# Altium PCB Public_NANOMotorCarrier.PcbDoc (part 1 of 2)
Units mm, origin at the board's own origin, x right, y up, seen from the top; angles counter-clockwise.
Board outline 50 x 80 mm, 4 copper layers (Top, PWR, GND, Bottom), stack 1.612 mm thick; 200 components, 139 nets, 723 pads, 320 vias.
Unrouted connection lines stored in the file: 53.
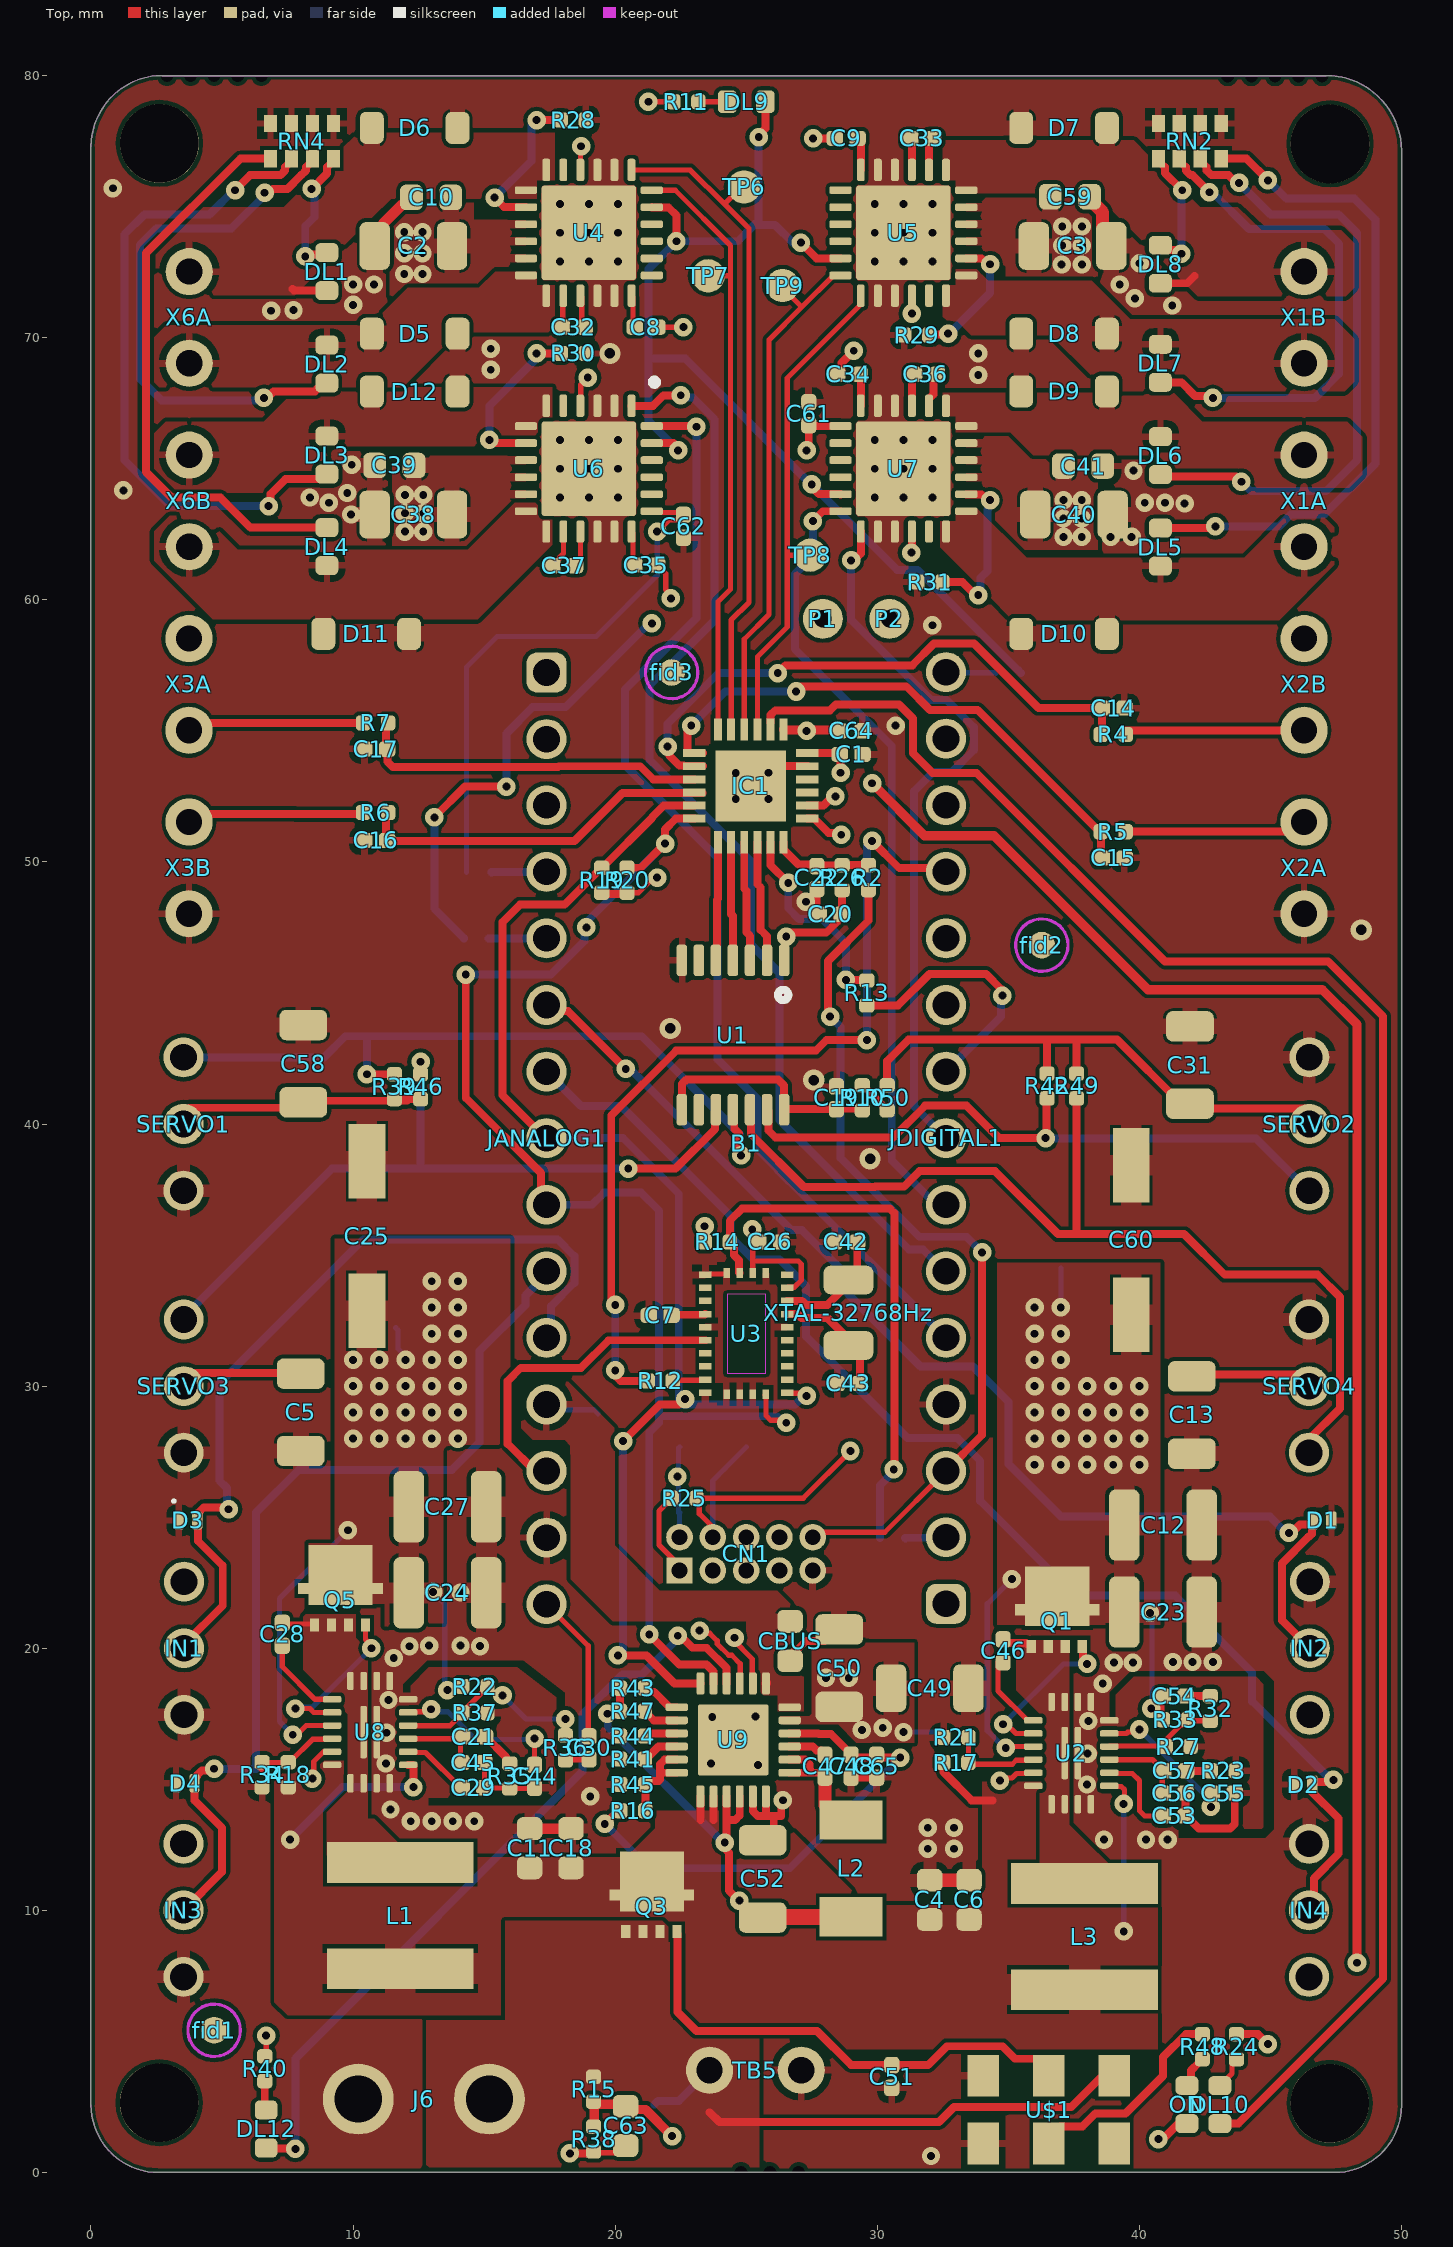
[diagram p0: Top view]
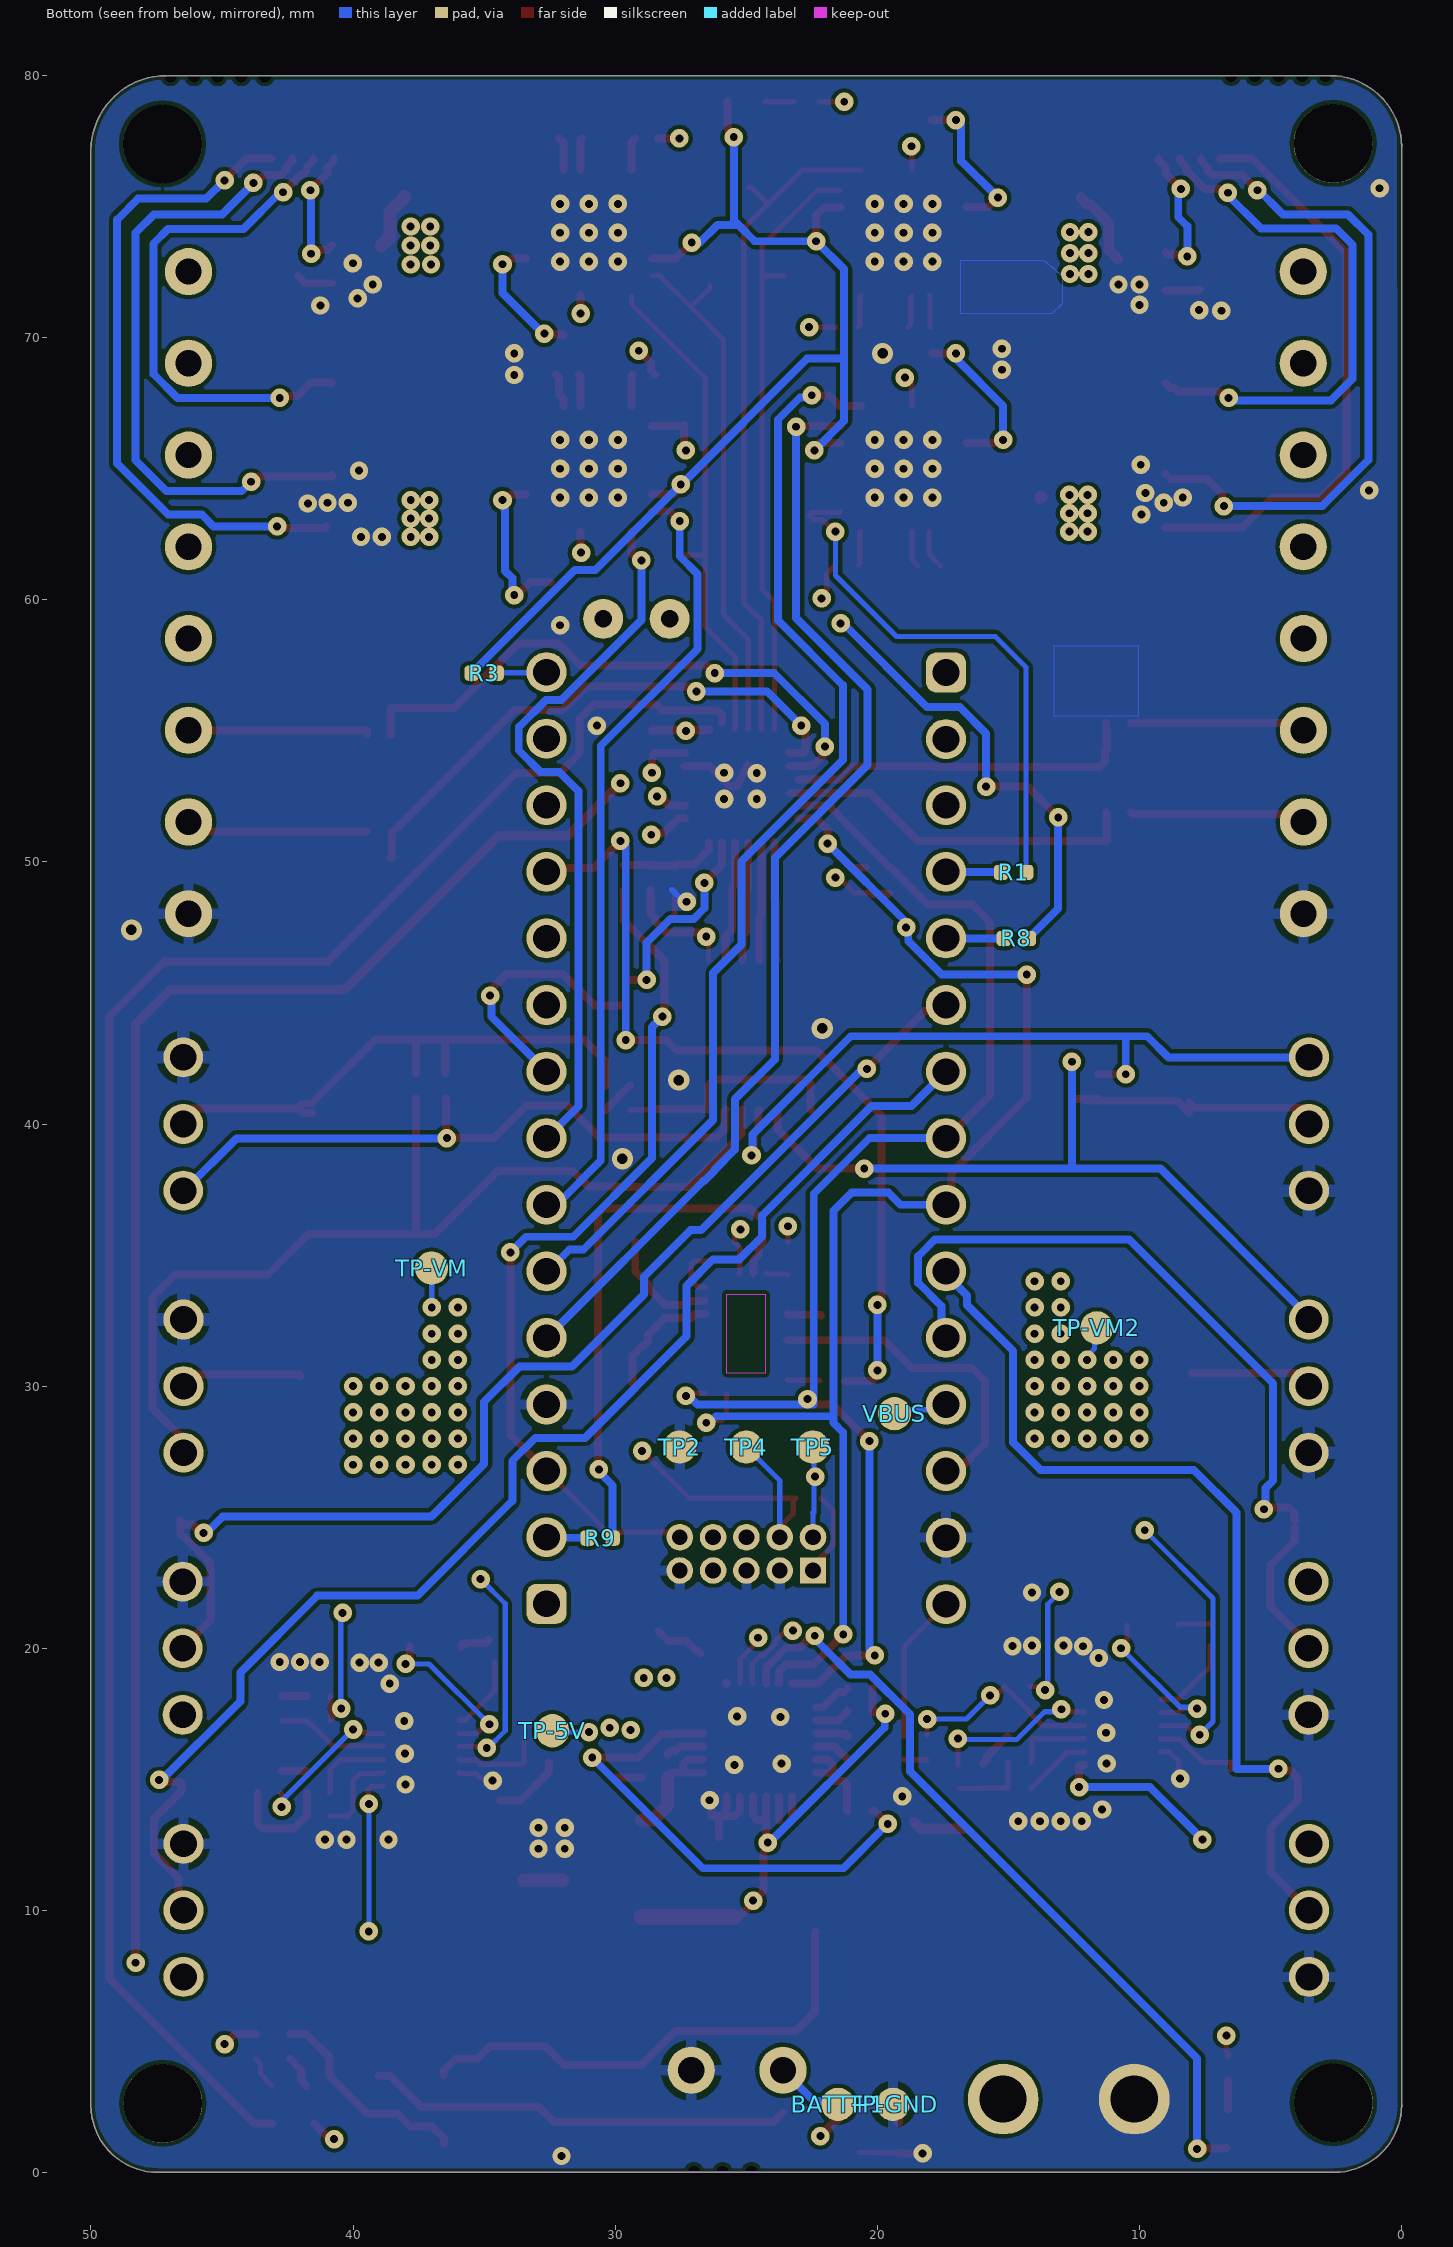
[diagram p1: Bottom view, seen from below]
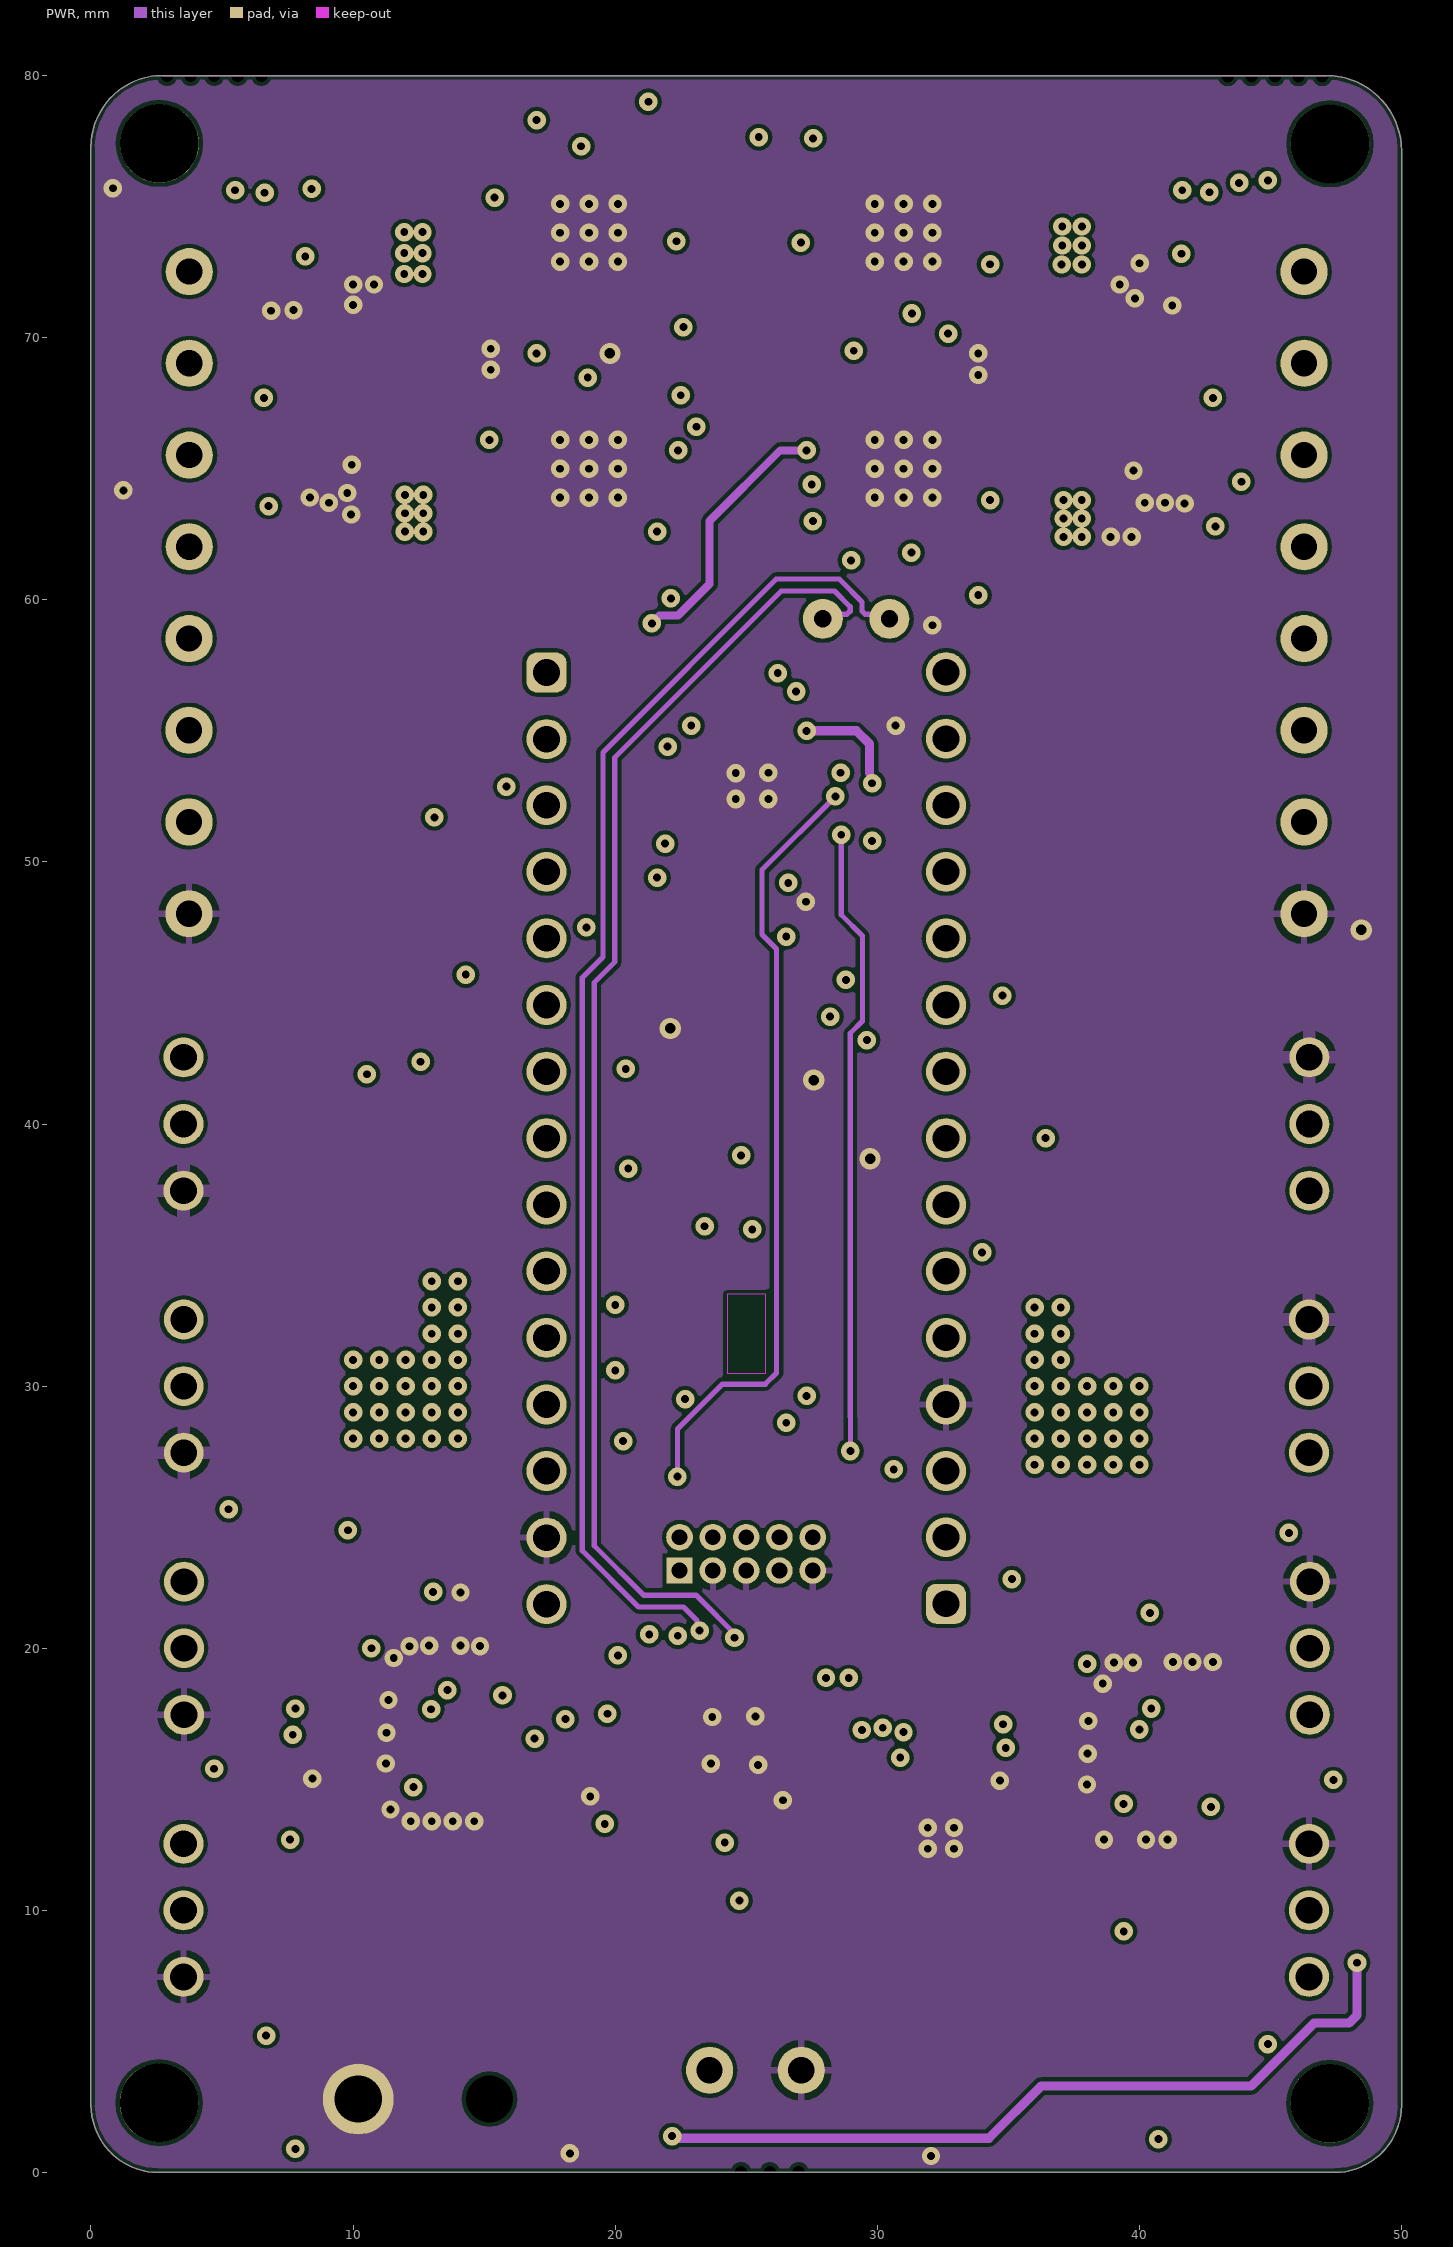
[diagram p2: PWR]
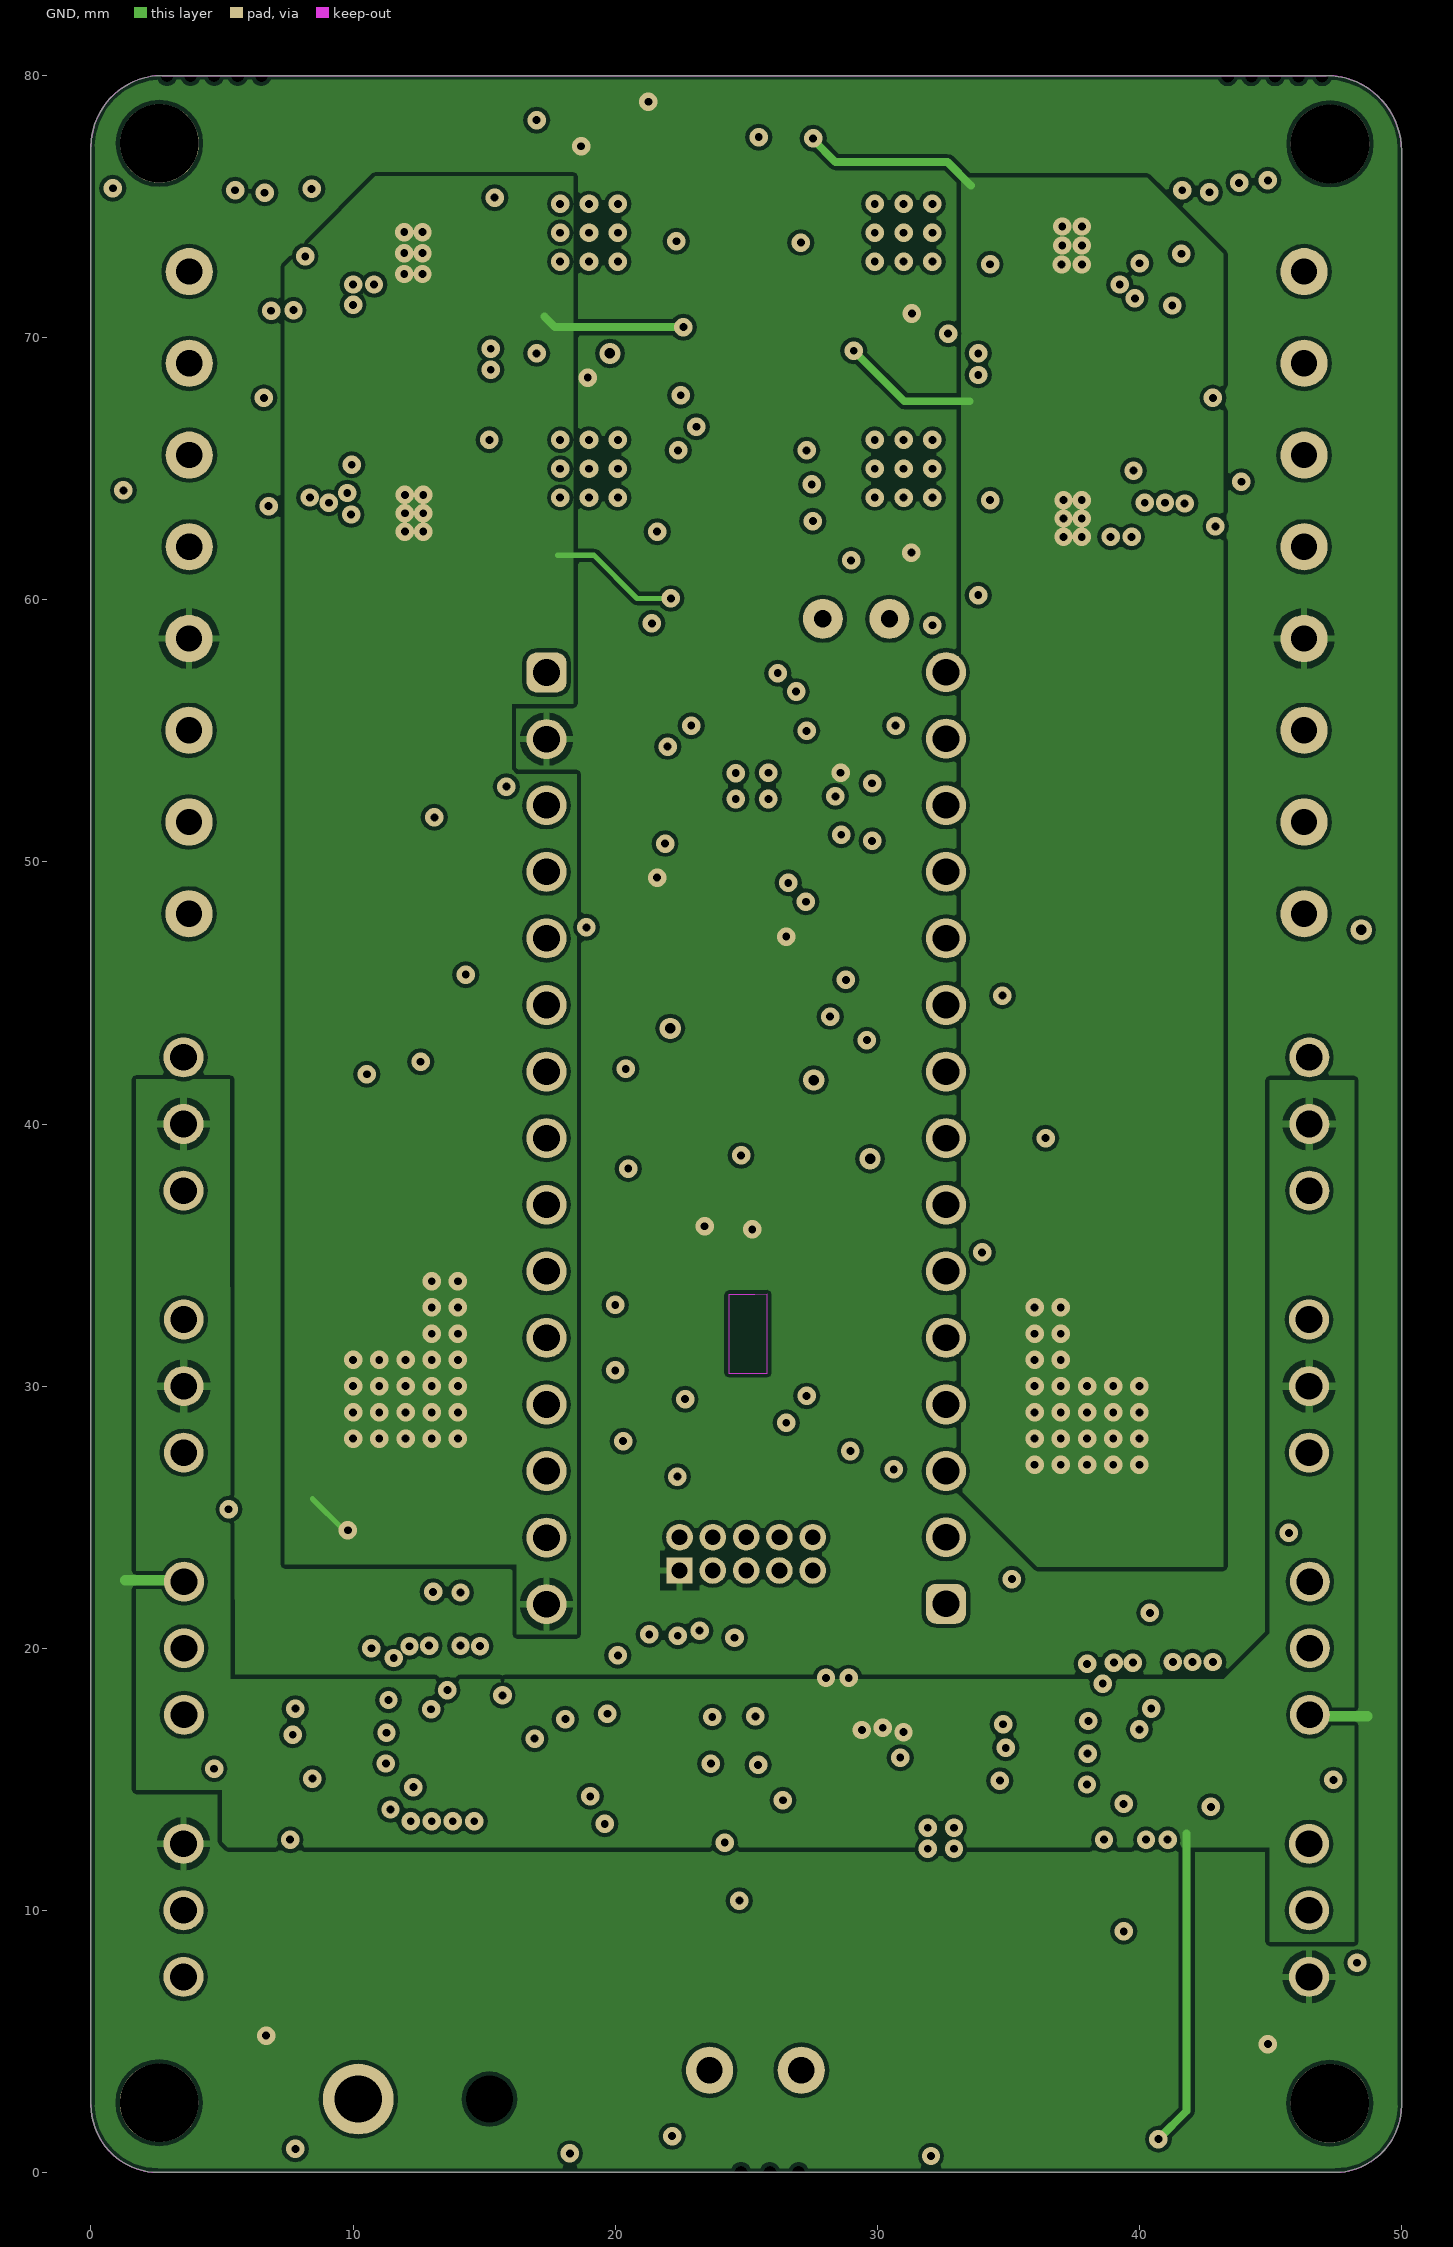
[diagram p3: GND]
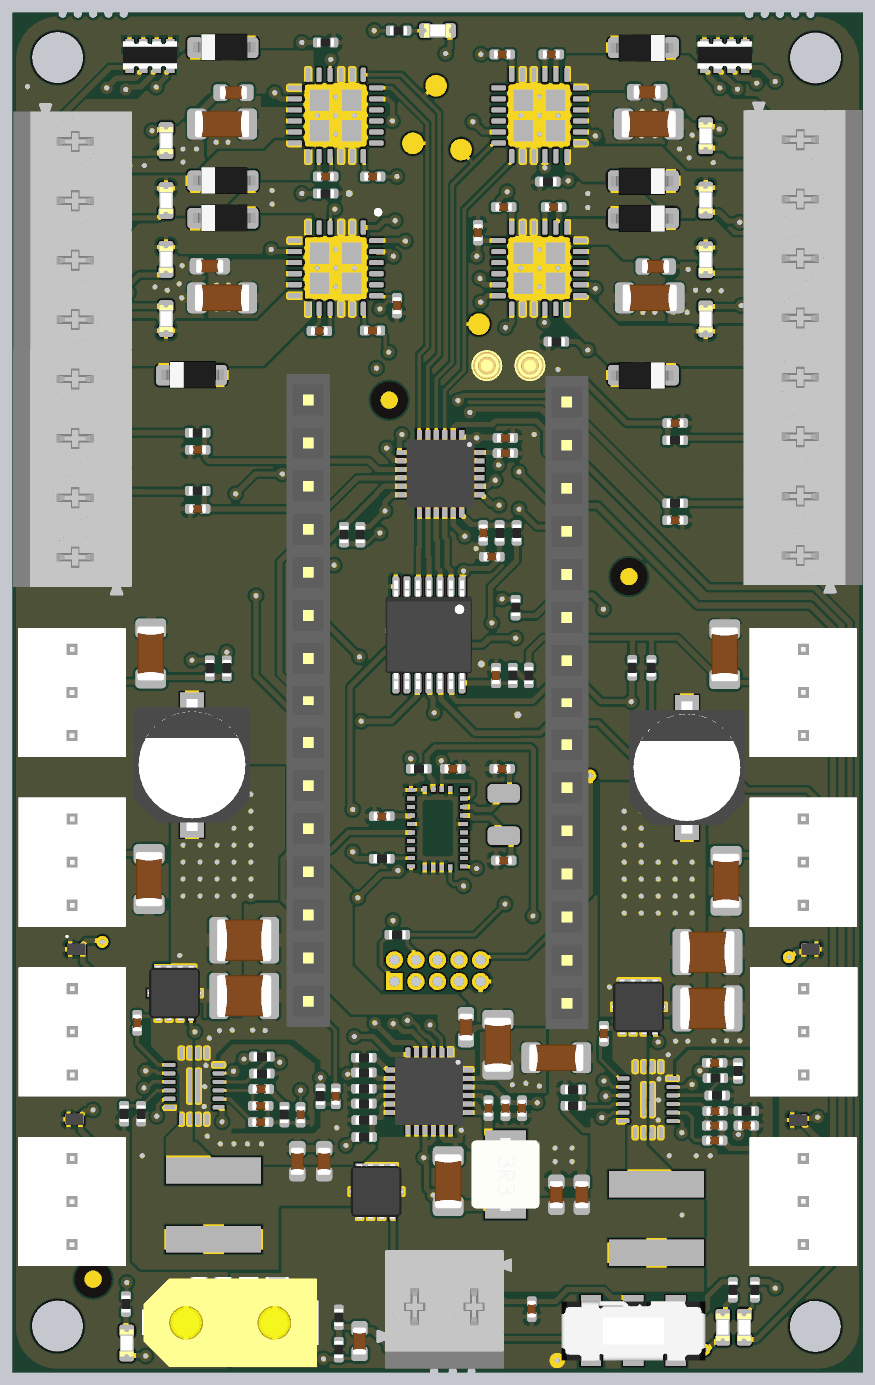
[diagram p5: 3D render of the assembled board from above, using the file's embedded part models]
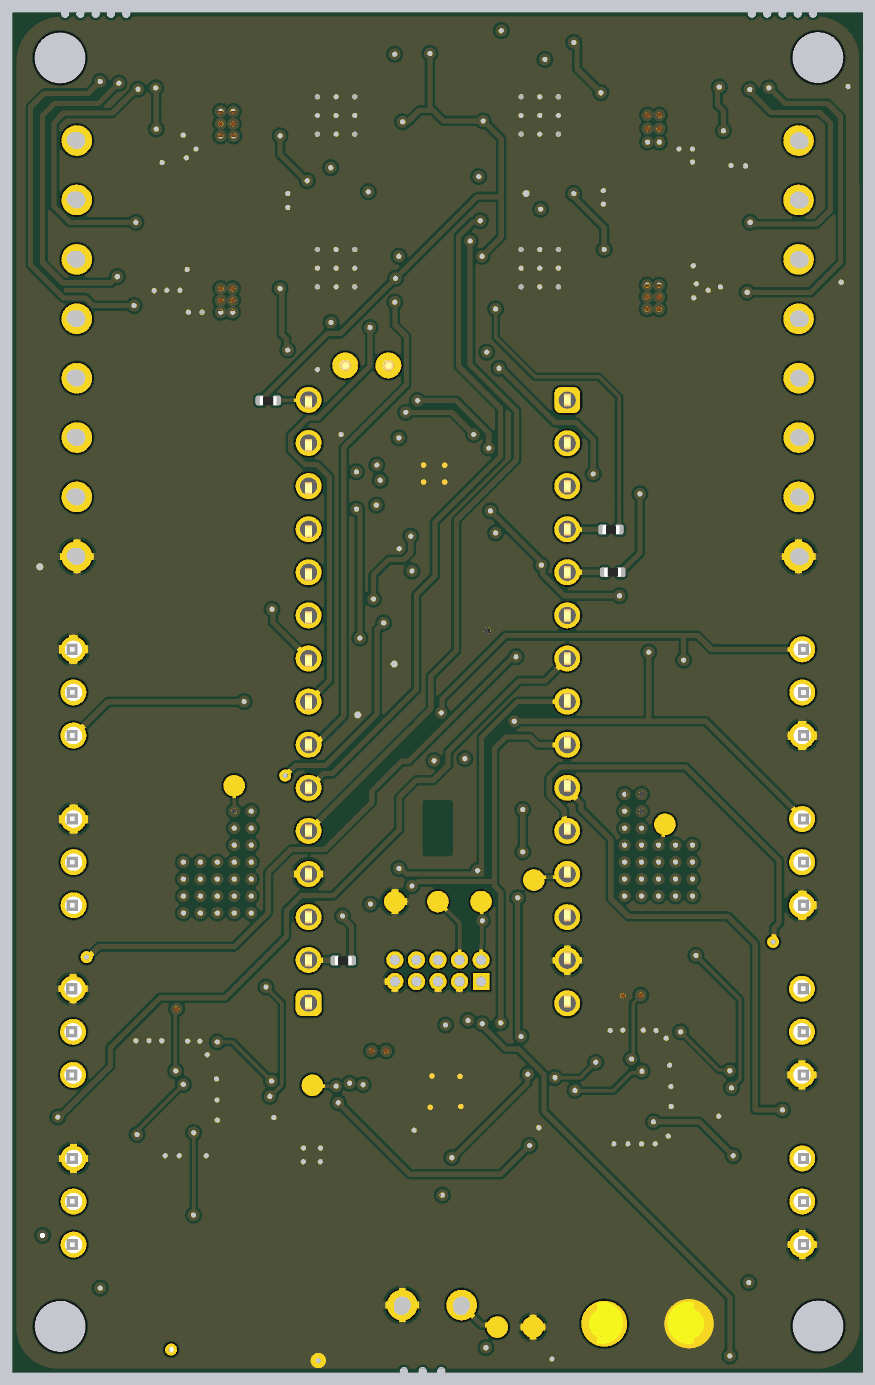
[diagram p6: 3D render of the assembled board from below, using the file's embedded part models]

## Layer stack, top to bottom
Top Solder: solder mask 0.01, Solder Resist, Dk 3.5
Top: signal copper 0.035
Dielectric 1: prepreg 0.356, FR-4, Dk 4.1
PWR: signal copper 0.035
Dielectric3: core 0.76, FR-4, Dk 4.8
GND: signal copper 0.035
Dielectric2: prepreg 0.356, FR-4, Dk 4.1
Bottom: signal copper 0.035
Bottom Solder: solder mask 0.0102, Solder Resist, Dk 3.5

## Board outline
47.437,0 2.583,0 cw(c2.583,2.583) 0,2.583 0,77.275 cw(c2.725,77.275) 2.725,80 47.122,80 cw(c47.122,77.122) 50,77.122 50,2.563 cw(c47.437,2.563)

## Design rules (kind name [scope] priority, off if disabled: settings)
Clearance "Clearance (Same Net)" [All] p1 off: gap=0.178 ignorepadtopadclearanceinfootprint=FALSE except(0.152: SMDPad-SMDPad SMDPad-THPad SMDPad-Via)
Clearance [All] p2: gap=0.15 ignorepadtopadclearanceinfootprint=TRUE
DiffPairsRouting [All] p1: maxlimit=0.254 minlimit=0.254 mostfreqgap=0.254 toplayer_minwidth=0.2 toplayer_maxwidth=0.381 toplayer_prefwidth=0.2 midlayer1_minwidth=0.2 midlayer1_maxwidth=0.381 midlayer1_prefwidth=0.2 midlayer2_minwidth=0.2 midlayer2_maxwidth=0.381 midlayer2_prefwidth=0.2 bottomlayer_minwidth=0.2 bottomlayer_maxwidth=0.381 bottomlayer_prefwidth=0.2 maxuncoupledlength=12.7
HoleSize [All] p1: absolutevalues=TRUE maxlimit=2540 minlimit=0.2 maxpercent=80.000 minpercent=20.000
HoleToHoleClearance NANO-CONNECTORS [InComponent('B1') vs InComponent('JDIGITAL1') or InComponent('JANALOG1')] p1: gap=0 allowstackedmicrovias=TRUE
HoleToHoleClearance mdDrill [All] p2: gap=0.254 allowstackedmicrovias=TRUE
MinimumSolderMaskSliver [All] p1 off: minsoldermaskwidth=0.254
PasteMaskExpansion Expansion_SMDPaste_OFF [InPadClass('SMDPaste_OFF')] p1: expansion=0
PasteMaskExpansion mlMinCreamFrame [All] p2: expansion=0
PlaneConnect PlaneConnect_1 [All] p1: planeconnectstyle=Relief reliefexpansion=0.508 reliefentries=4 reliefconductorwidth=0.254 reliefairgap=0.254
PolygonConnect VIA [IsVia] p1: connectstyle=Direct reliefconductorwidth=0.254 reliefentries=4 polygonreliefangle="90 Angle" airgapwidth=0.254
PolygonConnect SW_pad [(ObjectKind = 'Pad') And (Net = 'SW')] p2: connectstyle=Direct reliefconductorwidth=0.254 reliefentries=4 polygonreliefangle="90 Angle" airgapwidth=0.254
PolygonConnect +VM2_pad [(ObjectKind = 'Via') And (Net = '+VM2')] p3: connectstyle=Direct reliefconductorwidth=0.254 reliefentries=4 polygonreliefangle="90 Angle" airgapwidth=0.254
PolygonConnect VBATT_PADs [(ObjectKind = 'Pad') And (Net = 'VBATT')] p4: connectstyle=Direct reliefconductorwidth=0.254 reliefentries=4 polygonreliefangle="90 Angle" airgapwidth=0.254
PolygonConnect BATT+1_Pad [(ObjectKind = 'Pad') And (Net = 'BATT+1')] p5: connectstyle=Direct reliefconductorwidth=0.254 reliefentries=4 polygonreliefangle="90 Angle" airgapwidth=0.254
PolygonConnect GNDVias [IsVia and InNet('GND')] p6: connectstyle=Direct reliefconductorwidth=0.254 reliefentries=4 polygonreliefangle="90 Angle" airgapwidth=0.254
PolygonConnect MotorDriverGNDPads [IsComponentPad and InNet('GND') and InComponent('U4','U5','U6','U7')] p7: connectstyle=Direct reliefconductorwidth=0.254 reliefentries=4 polygonreliefangle="90 Angle" airgapwidth=0.254
PolygonConnect PolygonConnect_For_PolygonThermal_ON_Width120000_Gap100000 [InPolygonClass('PolygonThermal_ON_Width120000_Gap100000')] p8: connectstyle=Relief reliefconductorwidth=0.305 reliefentries=4 polygonreliefangle="90 Angle" airgapwidth=0.254
PolygonConnect PolygonConnect_For_PolygonThermal_OFF [InPolygonClass('PolygonThermal_OFF')] p9: connectstyle=Direct reliefconductorwidth=0.254 reliefentries=4 polygonreliefangle="90 Angle" airgapwidth=0.254
PolygonConnect PolygonConnect_For_PolygonThermal_ON_Width160000_Gap100000 [InPolygonClass('PolygonThermal_ON_Width160000_Gap100000')] p10: connectstyle=Relief reliefconductorwidth=0.406 reliefentries=4 polygonreliefangle="90 Angle" airgapwidth=0.254
PolygonConnect [All] p11: connectstyle=Relief reliefconductorwidth=0.254 reliefentries=4 polygonreliefangle="90 Angle" airgapwidth=0.254
RoomDefinition NANOMotorCarrierV0.1_IMU [InComponentClass('NANOMotorCarrierV0.1_IMU')] p1 off: confinementstyle=ConfineIn formatcopy=TRUE lockcomponents=FALSE outline 0,0 50.8,0 50.8,25.4 0,25.4
RoomDefinition NANOMotorCarrierV0.1_DRV [InComponentClass('NANOMotorCarrierV0.1_DRV')] p2 off: confinementstyle=ConfineIn formatcopy=TRUE lockcomponents=FALSE outline 0,0 50.8,0 50.8,25.4 0,25.4
RoomDefinition NANOMotorCarrierV0.1_PWR [InComponentClass('NANOMotorCarrierV0.1_PWR')] p3 off: confinementstyle=ConfineIn formatcopy=TRUE lockcomponents=FALSE outline 0,0 50.8,0 50.8,80.7 0,80.7
RoutingVias [All] p1: holewidth=0.3 width=0.706 viastyle="Through Hole" minholewidth=0.3 minwidth=0.706 maxholewidth=2.54 maxwidth=2.54
SilkToSolderMaskClearance [IsPad] p1 off: minsilkscreentomaskgap=0.1 clearancetoexposedcopper=TRUE
SolderMaskExpansion [(ObjectKind = 'Via')] p1 off: expansion=0.102 istentingtop=FALSE
SolderMaskExpansion Expansion_SMDSolder_OFF [InPadClass('SMDSolder_OFF')] p2: expansion=0 istentingtop=FALSE
SolderMaskExpansion mlMinStopFrame [All] p3: expansion=0.1 istentingtop=FALSE
Width [All] p1: maxlimit=254 minlimit=0.2 preferedwidth=0.2 minimp=50.000000 maximp=50.000000 favimp=50.000000
23 further rules are at their usual default settings.

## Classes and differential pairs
component class NANOMotorCarrierV0.1_IMU: C7 C26 C42 C43 R12 R14 U3 XTAL-32768Hz
component class NANOMotorCarrierV0.1_PWR: BATT+1 C4 C6 C11 C12 C18 C21 C23 C24 C27 C28 C29 C30 C44 C45 C46 C47 C48 C49 C50 C51 C52 C53 C54 C55 C56 C57 C63 C64 C65 CBUS DL12 J6 L1 L2 L3 ON P1 P2 Q1 Q3 Q5 R15 R16 R17 R18 R21 R22 R23 R27 R32 R33 R34 R35 R36 R37 R38 R40 R41 R43 R44 R45 R47 R48 TB5 TP-5V TP-GND TP-VM TP-VM2 U2 U8 U9 U$1 VBUS
component class NANOMotorCarrierV0.1_DRV: B1 C1 C2 C3 C5 C8 C9 C10 C13 C14 C15 C16 C17 C19 C20 C22 C25 C31 C32 C33 C34 C35 C36 C37 C38 C39 C40 C41 C58 C59 C60 C61 C62 CN1 D1 D2 D3 D4 D5 D6 D7 D8 D9 D10 D11 D12 DL1 DL2 DL3 DL4 DL5 DL6 DL7 DL8 DL9 DL10 fid1 fid2 fid3 IC1 IN1 IN2 IN3 IN4 JANALOG1 JDIGITAL1 R1 R2 R3 R4 R5 R6 R7 R8 R9 R10 R11 R13 R19 R20 R24 R25 R26 R28 R29 R30 R31 R39 R42 R46 R49 R50 RN2 RN4 SERVO1 SERVO2 SERVO3 SERVO4 TP2 TP4 TP5 TP6 TP7 TP8 TP9 U1 U4 U5 U6 U7 X1A X1B X2A X2B X3A X3B X6A X6B
polygon class PolygonThermal_ON_Width120000_Gap100000: Polygon_1_Net_+5V Polygon_2_Net_+5V Polygon_2_Net_M3- Polygon_3_Net_+VM
polygon class PolygonThermal_ON_Width160000_Gap100000: Polygon_2_Net_GND
pad class SMDPaste_OFF: TP2-X TP4-X U4-9 U7-9 U$33-P$1 U$34-P$1 U$35-P$1
differential pair USB: +USB_P -USB_N

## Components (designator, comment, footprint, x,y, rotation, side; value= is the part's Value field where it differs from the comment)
B1 "Nano Socket" "Nano Socket-Footprint-1" 16.11,61.05 r270 top
BATT+1 "CMP-018-0006-A.4" TP-1.27MM#1 21.5,2.6 r90 bottom
C1 "GRM155R61H104KE19D" CAP-0402 29,54.1 r180 top value=100nF
C2 "GRM31CR61H106KA12L" CAP-1206 12.3,73.5 r0 top value=10µF
C3 "GRM31CR61H106KA12L" CAP-1206 37.45,73.5 r180 top value=10µF
C4 "CL10A226MO7JZNC" CAP-0603 32,10.4 r270 top value=22µF
C5 "CL31A107MPHNNNE" CAP-1206 8,29 r90 top value=100µF
C6 "CL10A226MO7JZNC" CAP-0603 33.5,10.4 r270 top value=22µF
C7 "GRM155R61H104KE19D" CAP-0402 21.717,32.7 r0 top value=100nF
C8 "GRM155R61H104KE19D" CAP-0402 21.174,70.4 r0 top value=100nF
C9 "GRM155R61H104KE19D" CAP-0402 28.81,77.6 r180 top value=100nF
C10 "C0603C105K3PACTU" CAP-0603 12.975,75.35 r0 top value=1µF
C11 "CL10A226MO7JZNC" CAP-0603 16.737,12.371 r270 top value=22µF
C12 "C1210C226K3PACTU" CAP-1210 40.9,24.7 r180 top value=22µF
C13 "CL31A107MPHNNNE" CAP-1206 42,28.9 r90 top value=100µF
C14 "C0402C103K5RACTU" CAP-0402 39,55.87 r180 top value=10nF
C15 "C0402C103K5RACTU" CAP-0402 39,50.15 r0 top value=10nF
C16 "C0402C103K5RACTU" CAP-0402 10.86,50.82 r0 top value=10nF
C17 "C0402C103K5RACTU" CAP-0402 10.86,54.3 r180 top value=10nF
C18 "CL10A226MO7JZNC" CAP-0603 18.313,12.371 r270 top value=22µF
C19 "GRM155R61H104KE19D" CAP-0402 28.439,40.999 r270 top value=100nF
C20 "GRM155R61H104KE19D" CAP-0402 28.2,48 r0 top value=100nF
C21 "CC0402KRX7R9BB682" CAP-0402 14.6,16.625 r180 top value=6.8nF
C22 "GRM155R61H104KE19D" CAP-0402 27.694,49.4 r270 top value=100nF
C23 "C1210C226K3PACTU" CAP-1210 40.9,21.38 r180 top value=22µF
C24 "C1210C226K3PACTU" CAP-1210 13.6,22.115 r180 top value=22µF
C25 "EEEFTE221XAP" CAPAE7866X80L 10.53,35.726 r90 top
C26 "GRM155R61H104KE19D" CAP-0402 25.9,35.5 r180 top value=100nF
C27 "C1210C226K3PACTU" CAP-1210 13.6,25.4 r180 top value=22µF
C28 "GRM155R61H104KE19D" CAP-0402 7.3,20.53 r270 top value=100nF
C29 "CC0402MRX5R5BB225" CAP-0402 14.575,14.677 r180 top value=2.2µF
C30 "C0402C182J3GAC7867" CAP-0402 19,16.2 r270 top value=1.8nF
C31 "CL31A107MPHNNNE" CAP-1206 41.925,42.25 r270 top value=100µF
C32 "GRM155R61H104KE19D" CAP-0402 18.4,70.4 r0 top value=100nF
C33 "GRM155R61H104KE19D" CAP-0402 31.7,77.6 r180 top value=100nF
C34 "GRM155R61H104KE19D" CAP-0402 28.9,68.6 r180 top value=100nF
C35 "GRM155R61H104KE19D" CAP-0402 21.165,61.325 r0 top value=100nF
C36 "GRM155R61H104KE19D" CAP-0402 31.835,68.6 r180 top value=100nF
C37 "GRM155R61H104KE19D" CAP-0402 18.035,61.3 r0 top value=100nF
C38 "GRM31CR61H106KA12L" CAP-1206 12.3,63.25 r0 top value=10µF
C39 "C0603C105K3PACTU" CAP-0603 11.575,65.125 r0 top value=1µF
C40 "GRM31CR61H106KA12L" CAP-1206 37.5,63.25 r180 top value=10µF
C41 "C0603C105K3PACTU" CAP-0603 37.85,65.1 r180 top value=1µF
C42 "C0402C220J5GAC7411" CAP-0402 28.8,35.5 r0 top value=22pF
C43 "C0402C220J5GAC7411" CAP-0402 28.9,30.1 r0 top value=22pF
C44 "C0402C103K5RACTU" CAP-0402 16.925,15.115 r90 top value=10nF
C45 "GRM1555C1H151FA01D" CAP-0402 14.575,15.64 r0 top value=150pF
C46 "GRM155R61H104KE19D" CAP-0402 34.8,19.9 r270 top value=100nF
C47 "GRM155R61H473KE14D" CAP-0402 28,15.5 r270 top value=47nF
C48 "CC0402MRX5R5BB225" CAP-0402 29,15.5 r270 top value=2.2µF
C49 "GRM31CR61H106KA12L" CAP-1206 32,18.475 r180 top value=10µF
C50 "GRM31CR61H106KA12L" CAP-1206 28.55,19.242 r270 top value=10µF
C51 "C0402C103K5RACTU" CAP-0402 30.55,3.66 r90 top value=10nF
C52 "GRM31CR61H106KA12L" CAP-1206 25.625,11.2 r270 top value=10µF
C53 "CC0402MRX5R5BB225" CAP-0402 41.325,13.6 r180 top value=2.2µF
C54 "C0402C182J3GAC7867" CAP-0402 41.325,18.175 r0 top value=1.8nF
C55 "C0402C103K5RACTU" CAP-0402 43.2,14.475 r180 top value=10nF
C56 "GRM1555C1H151FA01D" CAP-0402 41.325,14.475 r0 top value=150pF
C57 "CC0402KRX7R9BB682" CAP-0402 41.35,15.325 r180 top value=6.8nF
C58 "CL31A107MPHNNNE" CAP-1206 8.1,42.3 r270 top value=100µF
C59 "C0603C105K3PACTU" CAP-0603 37.35,75.375 r180 top value=1µF
C60 "EEEFTE221XAP" CAPAE7866X80L 39.691,35.576 r90 top
C61 "GRM1555C1H111JA01D" CAP-0402 27.384,67.1 r270 top value=110pF
C62 "GRM1555C1H111JA01D" CAP-0402 22.6,62.8 r90 top value=110pF
C63 "C0603C105K3PACTU" CAP-0603 20.4,1.775 r270 top value=1µF
C64 "GRM155R61H104KE19D" CAP-0402 29,55 r180 top value=100nF
C65 "CC0402MRX5R5BB225" CAP-0402 29.975,15.5 r270 top value=2.2µF
CBUS "C0603C105K3PACTU" CAP-0603 26.675,20.275 r270 top value=1µF
CN1 "HPH2-A-10-SGA" PINHEAD_2X05_127 24.995,23.6 r90 top
D1 "DESD3V3S1BL-7B" X1-DFN1006-2 46.975,24.875 r180 top
D2 "DESD3V3S1BL-7B" X1-DFN1006-2 46.25,14.8 r0 top
D3 "DESD3V3S1BL-7B" X1-DFN1006-2 3.7,24.875 r0 top
D4 "DESD3V3S1BL-7B" X1-DFN1006-2 3.6,14.85 r0 top
D5 "PMEG6020AELRX" SOD123-1 12.35,70.15 r0 top
D6 "PMEG6020AELRX" SOD123-1 12.35,78 r0 top
D7 "PMEG6020AELRX" SOD123-1 37.125,78 r180 top
D8 "PMEG6020AELRX" SOD123-1 37.125,70.15 r180 top
D9 "PMEG6020AELRX" SOD123-1 37.125,67.95 r180 top
D10 "PMEG6020AELRX" SOD123-1 37.125,58.7 r180 top
D11 "PMEG6020AELRX" SOD123-1 10.5,58.7 r0 top
D12 "PMEG6020AELRX" SOD123-1 12.35,67.94 r0 top
DL1 "KPT-1608YC" LEDC1608X80N-AK 9,72.52 r270 top
DL2 "KPT-1608YC" LEDC1608X80N-AK 9,68.99 r90 top
DL3 "KPT-1608YC" LEDC1608X80N-AK 9,65.52 r90 top
DL4 "KPT-1608YC" LEDC1608X80N-AK 9,62.03 r270 top
DL5 "KPT-1608YC" LEDC1608X80N-AK 40.8,62.01 r270 top
DL6 "KPT-1608YC" LEDC1608X80N-AK 40.8,65.5 r90 top
DL7 "KPT-1608YC" LEDC1608X80N-AK 40.8,69.02 r90 top
DL8 "KPT-1608YC" LEDC1608X80N-AK 40.8,72.8 r270 top
DL9 "KPT-1608SECK" LEDC1608X80N-AK 25,79 r180 top
DL10 "KPT-1608SECK" LEDC1608X80N-AK 43.07,2.59 r90 top
DL12 "KPT-1608SECK" LEDC1608X80N-AK 6.684,1.66 r90 top
fid1 "Fiducial mark 1.5mm" FIDUCIAL-1.5 4.7,5.425 r0 top
fid2 "Fiducial mark 1.5mm" FIDUCIAL-1.5 36.275,46.825 r0 top
fid3 "Fiducial mark 1.5mm" FIDUCIAL-1.5 22.152,57.225 r0 top
IC1 "ATSAM-D11-D14A-MUT" VQFN24#1 25.174,52.899 r0 top
IN1 "LHA-03-TS" MODULINO-3 3.55,20 r90 top
IN2 "LHA-03-TS" MODULINO-3 46.5,20 r270 top
IN3 "LHA-03-TS" MODULINO-3 3.53,10 r90 top
IN4 "LHA-03-TS" MODULINO-3 46.47,10 r270 top
J6 "XT30UPB-M" XT30UPB-M-Footprint-1 15.2,2.8 r270 top
JANALOG1 "PINHD-1X15-NANO" "New footprint 1"#1 17.38,39.46 r270 top
JDIGITAL1 "PINHD-1X15-NANO-DIGITAL" PINHD-1X14_5VF 32.62,39.46 r270 top
L1 "SRP6050CA-1R2M" INDP6466X48N 11.8,9.8 r90 top
L2 "SRP4020TA-2R2M" SRP4020 29,11.6 r270 top
L3 "SRP6050CA-1R2M" INDP6466X48N 37.9,9 r90 top
ON "HSMG-C190" LEDC1608X80N-AK 41.811,2.59 r270 top
P1 "0929-7-15-20-7X-14-11-0" "New footprint 1"#2 27.921,59.272 r0 top
P2 "0929-7-15-20-7X-14-11-0" "New footprint 1"#2 30.461,59.272 r0 top
Q1 "AON7522E" DFN8#1 36.946,21.445 r90 top
Q3 "AON7407" DFN8#2 21.481,10.565 r90 top
Q5 "AON7522E" DFN8#1 9.6,22.255 r90 top
R1 "CRCW04020000Z0EDC" RES-0402 14.8,49.6 r0 bottom value=0
R2 "CRCW04020000Z0EDC" RES-0402 29.659,49.4 r270 top value=0
R3 "CRCW04020000Z0EDC" RES-0402 35,57.2 r0 bottom value=0
R4 "CRCW0402140RFKED" RES-0402 39,54.86 r0 top value=140
R5 "CRCW0402140RFKED" RES-0402 39,51.15 r0 top value=140
R6 "CRCW0402140RFKED" RES-0402 10.86,51.88 r180 top value=140
R7 "CRCW0402140RFKED" RES-0402 10.86,55.3 r180 top value=140
R8 "CRCW04020000Z0EDC" RES-0402 14.7,47.08 r0 bottom value=0
R9 "CRCW04020000Z0EDC" RES-0402 30.575,24.2 r180 bottom value=0
R10 "CRCW0402100KFKEDC" RES-0402 29.429,40.999 r90 top value=100k
R11 "CRCW0402330RJNED" RES-0402 22.7,79 r0 top value=330
R12 "CRCW04020000Z0EDC" RES-0402 21.717,30.2 r180 top value=0
R13 "CRCW04020000Z0EDC" RES-0402 29.6,45 r90 top value=0
R14 "CRCW040210K0FKED" RES-0402 23.9,35.5 r0 top value=10k
R15 "CRCW040210K0FKED" RES-0402 19.175,3.175 r90 top value=10k
R16 "CRCW04025K49FKED" RES-0402 20.675,13.8 r180 top value=5.49k
R17 "CRCW0402100KFKEDC" RES-0402 33,15.64 r180 top value=100k
R18 "CRCW0402100KFKEDC" RES-0402 7.525,15.175 r270 top value=100k
R19 "CRCW040210K0FKED" RES-0402 19.485,49.3 r270 top value=10k
R20 "CRCW040210K0FKED" RES-0402 20.45,49.3 r270 top value=10k
R21 "CRCW0402100KFKEDC" RES-0402 33,16.6 r0 top value=100k
R22 "RC0402FR-07300KL" RES-0402 14.65,18.54 r180 top value=300k
R23 "CRCW040227K0JNED" RES-0402 43.2,15.325 r180 top value=27k
R24 "CRCW0402330RJNED" RES-0402 43.7,4.8 r270 top value=330
R25 "CRCW040210K0FKED" RES-0402 22.625,25.725 r0 top value=10k
R26 "CRCW040210K0FKED" RES-0402 28.659,49.4 r90 top value=10k
R27 "RC0402FR-0734KL" RES-0402 41.475,16.25 r180 top value=34k
R28 "CRCW04026K81FKED" RES-0402 18.4,78.3 r180 top value=6.81k
R29 "CRCW04026K81FKED" RES-0402 31.5,70.1 r0 top value=6.81k
R30 "CRCW04026K81FKED" RES-0402 18.4,69.4 r180 top value=6.81k
R31 "CRCW04026K81FKED" RES-0402 32,60.675 r0 top value=6.81k
R32 "CRCW040216K0JNED" RES-0402 42.7,17.7 r90 top value=16k
R33 "RC0402FR-07300KL" RES-0402 41.375,17.275 r180 top value=300k
R34 "CRCW0402100KFKEDC" RES-0402 6.525,15.175 r90 top value=100k
R35 "CRCW040227K0JNED" RES-0402 15.975,15.125 r90 top value=27k
R36 "CRCW040216K0JNED" RES-0402 18.1,16.2 r270 top value=16k
R37 "RC0402FR-0734KL" RES-0402 14.65,17.54 r180 top value=34k
R38 "CRCW040232K4FKED" RES-0402 19.175,1.275 r90 top value=32.4k
R39 "CRCW040210K0FKED" RES-0402 11.575,41.425 r270 top value=10k
R40 "CRCW0402330RJNED" RES-0402 6.63,3.96 r90 top value=330
R41 "CRCW0402330RJNED" RES-0402 20.66,15.77 r180 top value=330
R42 "CRCW040210K0FKED" RES-0402 36.475,41.45 r90 top value=10k
R43 "CRCW040210K0FKED" RES-0402 20.66,18.475 r0 top value=10k
R44 "CRCW040210K0FKED" RES-0402 20.66,16.65 r0 top value=10k
R45 "CRCW040210K0FKED" RES-0402 20.675,14.8 r0 top value=10k
R46 "CRCW040210K0FKED" RES-0402 12.575,41.425 r270 top value=10k
R47 "CRCW040210K0FKED" RES-0402 20.66,17.6 r0 top value=10k
R48 "CRCW0402330RJNED" RES-0402 42.4,4.8 r90 top value=330
R49 "CRCW040210K0FKED" RES-0402 37.6,41.45 r90 top value=10k
R50 "CRCW0402100KFKEDC" RES-0402 30.375,41 r90 top value=100k
RN2 "CAY16-102J4LF" CAY16 41.92,77.5 r180 top value=1k
RN4 "CAY16-102J4LF" CAY16 8.05,77.5 r180 top value=1k
SERVO1 "LHA-03-TS-OUT" LHA-03-TS-OUT-Footprint-1 3.53,40 r90 top
SERVO2 "LHA-03-TS-OUT" LHA-03-TS-OUT-Footprint-1 46.48,40 r270 top
SERVO3 "LHA-03-TS-OUT" LHA-03-TS-OUT-Footprint-1 3.54,30 r90 top
SERVO4 "LHA-03-TS-OUT" LHA-03-TS-OUT-Footprint-1 46.47,30 r270 top
TB5 "MK125002GO" MK125002GO 25.35,3.9 r0 top
TP2 "CMP-018-0006-A.4" TP-1.27MM#2 27.54,27.675 r0 top
TP4 "CMP-018-0006-A.4" TP-1.27MM#2 25,27.675 r0 top
TP5 "CMP-018-0006-A.4" TP-1.27MM#3 24.995,25.5 r0 top
TP6 "CMP-018-0006-A.4" TP-1.27MM#1 24.917,75.749 r0 top
TP7 "CMP-018-0006-A.4" TP-1.27MM#1 23.547,72.358 r0 top
TP8 "CMP-018-0006-A.4" TP-1.27MM#1 27.44,61.7 r0 top
TP9 "CMP-018-0006-A.4" TP-1.27MM#1 26.384,71.989 r0 top
TP-5V "CMP-018-0006-A.4" TP-1.27MM#1 32.397,16.852 r90 bottom
TP-GND "CMP-018-0006-A.4" TP-1.27MM#1 19.4,2.6 r270 bottom
TP-VM "CMP-018-0006-A.4" TP-1.27MM#1 37.005,34.501 r90 bottom
TP-VM2 "CMP-018-0006-A.4" TP-1.27MM#1 11.625,32.225 r90 bottom
U1 "LSF0204QPWRQ1" TSOP65P640X120-14L 24.5,43.4 r180 top
U2 "MP3428AGL-P" QFN50P300X400X100-20N 37.4,16 r0 top
U3 "BNO055-A.4" BNO055 25,32 r270 top
U4 "MP6522GU-P" QFN65P500X500X100_HS-25N 18.995,74 r270 top
U5 "MP6522GU-P" QFN65P500X500X100_HS-25N 30.995,74 r90 top
U6 "MP6522GU-P" QFN65P500X500X100_HS-25N 18.995,65 r270 top
U7 "MP6522GU-P" QFN65P500X500X100_HS-25N 30.995,65 r90 top
U8 "MP3428AGL-P" QFN50P300X400X100-20N 10.65,16.8 r0 top
U9 "BQ24195LRGET" VQFN24#2 24.5,16.5 r0 top
U$1 "CL-SB-22A-02T" CL-SB-22A 36.539,2.4 r0 top
VBUS "CMP-018-0006-A.4" TP-1.27MM#2 19.347,28.947 r0 top
X1A "MK125002GO" MK125002GO 46.28,63.77 r90 top
X1B "MK125002GO" MK125002GO 46.28,70.77 r90 top
X2A "MK125002GO" MK125002GO 46.28,49.77 r90 top
X2B "MK125002GO" MK125002GO 46.28,56.77 r90 top
X3A "MK125002GO" MK125002GO 3.74,56.77 r270 top
X3B "MK125002GO" MK125002GO 3.74,49.77 r270 top
X6A "MK125002GO" MK125002GO 3.75,70.77 r270 top
X6B "MK125002GO" MK125002GO 3.75,63.77 r270 top
XTAL-32768Hz "Q13FC1350000400" ABS07 28.9,32.8 r90 top

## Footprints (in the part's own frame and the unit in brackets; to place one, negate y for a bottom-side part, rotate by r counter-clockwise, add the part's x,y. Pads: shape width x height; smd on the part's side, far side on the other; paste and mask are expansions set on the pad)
ABS07 [mm]
  rrect50% 1.1x1.9 smd: 1(-1.25,0) 2(1.25,0)
  body extent -1.65,-0.83 1.65,0.83, height 0.9
BNO055 [mm]
  rect 0.25x0.475 smd: 1(-2.25,1.563) 6(-2.25,-1.563) 7(-1.75,-1.563) 8(-1.25,-1.563) 9(-0.75,-1.563) 10(-0.25,-1.563) 11(0.25,-1.563) 12(0.75,-1.563) 13(1.25,-1.563) 14(1.75,-1.563) 15(2.25,-1.563) 20(2.25,1.563) 21(1.75,1.563) 22(1.25,1.563) 23(0.75,1.563) 24(0.25,1.563) 25(-0.25,1.563) 26(-0.75,1.563) 27(-1.25,1.563) 28(-1.75,1.563)
  rect 0.375x0.25 smd: 2(-2.312,0.75) 3(-2.312,0.25) 4(-2.312,-0.25) 5(-2.312,-0.75) 16(2.312,-0.75) 17(2.312,-0.25) 18(2.312,0.25) 19(2.312,0.75)
  body extent -2.56,-1.9 2.66,1.85, height 0.6
CAP-0402 [mm] "Chip Capacitor, 2-Leads, Body  0402 (in) 1005 (mm), IPC Medium Density"
  rrect52% 0.63x0.58 smd mask+0: 1(-0.435,0) 2(0.435,0)
  body extent -0.5,-0.25 0.5,0.25, height 0.5
CAP-0603 [mm] "Chip Capacitor, Body 0603 imperial,1.6x0.8mm, IPC High Density"
  rrect51% 0.87x0.97 smd mask+0: 1(-0.75,0) 2(0.75,0)
  body extent -0.8,-0.4 0.8,0.4, height 0.8
CAP-1206 [mm] "Chip Capacitor, 2-Leads, 1206 (in) 3216 (mm), IPC Medium Density"
  rrect43% 1.16x1.82 smd mask+0: 1(-1.475,0) 2(1.475,0)
  body extent -1.6,-0.8 1.6,0.8, height 1.6
CAP-1210 [mm] "Chip Capacitor, Body 1210 imperial, 3.2x2.5mm, IPC High Density"
  rrect43% 1.16x2.72 smd mask+0: 1(-1.475,0) 2(1.475,0)
  body extent -1.6,-1.25 1.6,1.25, height 2.5
CAPAE7866X80L [mm] "Aluminum Electrolytic Capacitor, Body 6.60x6.60x8.00mm, IPC High Density"
  rect 2.85x1.4 smd: 1(2.85,0) 2(-2.85,0)
  body extent -3.9,-3.4 3.9,3.4, height 8
CAY16 [mm]
  rect 0.5x0.65 smd: 1(-1.2,-0.675) 2(-0.4,-0.675) 3(0.4,-0.675) 4(1.2,-0.675) 5(1.2,0.675) 6(0.4,0.675) 7(-0.4,0.675) 8(-1.2,0.675)
  body extent -1.6,-0.86 1.6,0.74, height 0.5
CL-SB-22A [mm]
  rect 1.2x1.6 smd: 1(-2.5,-1.29) 2(0,-1.29) 3(2.5,-1.29) 4(-2.5,1.29) 5(0,1.29) 6(2.5,1.29)
  body extent -4.25,-1.78 4.25,1.72, height 5.51
DFN8#1 [mm]
  rect 0.5x0.35 smd: 1(-1.375,-0.875) 2(-1.375,-0.225) 2(-1.375,0.425) 2(-1.375,1.075)
  rect 2.28x2.45 smd: 3(0.535,0.081)
  rect 0.43x0.4 smd: M1(0.025,1.495) M2(0.025,-1.335)
  body extent -1.57,-1.45 1.63,1.66, height 0.91
DFN8#2 [mm]
  rect 0.5x0.35 smd: 1(-1.375,1.075) 2(-1.375,0.425) 3(-1.375,-0.225) 4(-1.375,-0.875)
  rect 2.28x2.45 smd: 5(0.535,0.081)
  rect 0.43x0.4 smd: M1(0.025,1.495) M2(0.025,-1.335)
  body extent -1.57,-1.45 1.63,1.66, height 0.91
FIDUCIAL-1.5 [mil]
  rrect100% 40x40 smd paste-100: 1(0,0)
  Top keep-out circle w5: c0,0 r39.37
INDP6466X48N [mm] "Precision Wire Wound Inductor, 2-Leads, Body 6.40x6.60mm, IPC Medium Density"
  rect 1.55x5.6 smd: 1(-2.025,0) 2(2.025,0)
  body extent -3.2,-3.3 3.2,3.3, height 4.8
LEDC1608X80N-AK [mm]
  rrect50% 0.72x0.87 smd: A(0.725,0) C(-0.725,0)
  body extent -0.8,-0.4 0.8,0.4, height 0.79
LHA-03-TS-OUT-Footprint-1 [mil]
  round 60 hole 40 unplated: 1(100,0) 2(0,0) 3(-100,0)
  body extent -150,-122 150,128, height 401
MK125002GO [mm]
  round 1.8 hole 1 unplated: 1(-1.75,0) 2(1.75,0)
  body extent -3.95,-3.75 4.05,3.25, height 8.31
MODULINO-3 [mil]
  round 60 hole 40 unplated: 1(100,0) 2(0,0) 3(-100,0)
  body extent -150,-122 150,128, height 401
"Nano Socket-Footprint-1" [mil]
  rrect50% 60x60 hole 40 unplated paste-100: 1(150.59,50) 16(1549.41,650)
  round 60 hole 40 unplated paste-100: 2(250.59,50) 3(350,50) 4(450,50) 5(550,50) 6(650,50) 7(750,50) 8(850,50) 9(950,50) 10(1050,50) 11(1150,50) 12(1250,50) 13(1350,50) 14(1450,50) 15(1550,50) 17(1449.41,650) 18(1350,650) 19(1250,650) 20(1150,650) 21(1050,650) 22(950,650) 23(850,650) 24(750,650) 25(650,650) 26(550,650) 27(450,650) 28(350,650) 29(250,650) 30(150,650)
  rrect100% 39.37x39.37 on Mech15 paste+0: +3V3(1545.98,249.61) GND(1545.98,449.61) RESETN(1645.98,449.61) SWCLK(1545.98,349.61) SWDIO(1645.98,249.61)
  rrect100% 39.37x39.37 on Mech15 paste-100: N(70,564.61) P(70,464.61)
"New footprint 1"#1 [mil]
  rrect50% 60x60 hole 31.5 unplated paste-100: 1(-699.41,0)
  round 60 hole 31.5 unplated paste-100: 2(-599.41,0) 3(-500,0) 4(-400,0) 5(-300,0) 6(-200,0) 7(-100,0) 8(0,0) 9(100,0) 10(200,0) 11(300,0) 12(400,0) 13(500,0) 14(600,0) 15(700,0)
  body extent -760,-50 755,50, height 335
"New footprint 1"#2 [mil]
  round 60 hole 25.98 unplated: 1(0,0)
  body extent -37,-37 35,35, height 481
PINHD-1X14_5VF [mil]
  rrect50% 60x60 hole 31.5 unplated paste-100: 1(699.41,0)
  round 60 hole 31.5 unplated paste-100: 2(599.41,0) 3(500,0) 4(400,0) 5(300,0) 6(200,0) 7(100,0) 8(0,0) 9(-100,0) 10(-200,0) 11(-300,0) 12(-400,0) 13(-500,0) 14(-600,0) 15(-700,0)
  body extent -755,-50 760,50, height 335
PINHEAD_2X05_127 [mil]
  rect 38.73x38.73 / inner rect 38.74x38.74 / far side rect 38.73x38.73 hole 23.62 unplated: 1(-25,100)
  round 40 hole 23.62 unplated: 2(25,100) 3(-25,50) 4(25,50) 5(-25,0) 6(25,0) 7(-25,-50) 8(25,-50) 9(-25,-100) 10(25,-100)
QFN50P300X400X100-20N [mm] "QFN, 20-Leads, Body 3,00x4,00mm, Pitch 0,50mm, IPC Medium Density"
  rrect50% 0.7x0.25 smd: 1(-1.45,1.25) 2(-1.45,0.75) 3(-1.45,0.25) 4(-1.45,-0.25) 5(-1.45,-0.75) 6(-1.45,-1.25) 11(1.45,-1.25) 12(1.45,-0.75) 13(1.45,-0.25) 14(1.45,0.25) 15(1.45,0.75) 16(1.45,1.25)
  rrect50% 0.25x0.7 smd: 7(-0.75,-1.95) 8(-0.25,-1.95) 9(0.25,-1.95) 10(0.75,-1.95) 17(0.75,1.95) 18(0.25,1.95) 19(-0.25,1.95) 20(-0.75,1.95)
  rrect50% 0.25x2 smd: 21(-0.25,0) 22(0.25,0)
QFN65P500X500X100_HS-25N [mm] "QFN, 24-Leads, Body 5.00x5.00mm, Pitch 0.65mm, Thermal Pad 3.60x3.60mm, IPC Medium Density"
  rrect50% 0.85x0.3 smd: 1(-2.4,1.625) 2(-2.4,0.975) 3(-2.4,0.325) 4(-2.4,-0.325) 5(-2.4,-0.975) 6(-2.4,-1.625) 13(2.4,-1.625) 14(2.4,-0.975) 15(2.4,-0.325) 16(2.4,0.325) 17(2.4,0.975) 18(2.4,1.625)
  rrect50% 0.3x0.85 smd: 7(-1.625,-2.4) 8(-0.975,-2.4) 9(-0.325,-2.4) 10(0.325,-2.4) 11(0.975,-2.4) 12(1.625,-2.4) 19(1.625,2.4) 20(0.975,2.4) 21(0.325,2.4) 22(-0.325,2.4) 23(-0.975,2.4) 24(-1.625,2.4)
  rrect5% 3.6x3.6 smd paste-3.6: 25(0,0)
  body extent -2.5,-2.5 2.5,2.5, height 1
RES-0402 [mm] "Chip Resistor, 2-Leads, Body  0402 (in) 1005 (mm), IPC Medium Density"
  rrect51% 0.55x0.58 smd mask+0: 1(-0.475,0) 2(0.475,0)
  body extent -0.5,-0.25 0.5,0.25, height 0.34
SOD123-1 [mm]
  rrect50% 0.91x1.22 smd: A(1.635,0) C(-1.635,0)
  body extent -1.78,-0.78 1.92,0.82, height 1.27
SRP4020 [mm]
  rect 1.5x2.4 smd: 1(-1.85,0) 2(1.85,0)
  body extent -2.15,-2 2.15,2, height 1.9
TP-1.27MM#1 [mm]
  rrect100% 1.27x1.27 smd paste-2.54: X(0,0)
TP-1.27MM#2 [mm]
  rrect100% 1.27x1.27 smd far side paste-2.54: X(0,0)
TP-1.27MM#3 [mm]
  rrect100% 1.27x1.27 smd far side paste-2.54: X(-2.535,2.175)
TSOP65P640X120-14L [mm] "TSOP, 14-Leads, Body 5.00x4.40mm, Pitch 0.65mm, IPC High Density"
  rrect50% 0.4x1.2 smd: 1(-1.942,-2.845) 2(-1.292,-2.845) 3(-0.642,-2.845) 4(0.008,-2.845) 5(0.658,-2.845) 6(1.308,-2.845) 7(1.958,-2.845) 8(1.958,2.855) 9(1.308,2.855) 10(0.658,2.855) 11(0.008,2.855) 12(-0.642,2.855) 13(-1.292,2.855) 14(-1.942,2.855)
  silkscreen extent -2.1,-1.72 -1.71,-1.32, body extent -2.54,-3.2 2.56,3.2, height 1.2
VQFN24#1 [mm]
  rect 0.3x0.85 smd: 1(1.25,2.155) 2(0.75,2.155) 3(0.25,2.155) 4(-0.25,2.155) 5(-0.75,2.155) 6(-1.25,2.155) 13(-1.25,-2.155) 14(-0.75,-2.155) 15(-0.25,-2.155) 16(0.25,-2.155) 17(0.75,-2.155) 18(1.25,-2.155)
  rect 0.85x0.3 smd: 7(-2.155,1.25) 8(-2.155,0.75) 9(-2.155,0.25) 10(-2.155,-0.25) 11(-2.155,-0.75) 12(-2.155,-1.25) 19(2.155,-1.25) 20(2.155,-0.75) 21(2.155,-0.25) 22(2.155,0.25) 23(2.155,0.75) 24(2.155,1.25)
  rect 2.7x2.7 smd: EXP(0,0)
  body extent -2.05,-2.05 2.05,2.05, height 1
VQFN24#2 [mm]
  rrect50% 0.3x0.85 smd: 1(1.25,2.155) 2(0.75,2.155) 3(0.25,2.155) 4(-0.25,2.155) 5(-0.75,2.155) 6(-1.25,2.155) 13(-1.25,-2.155) 14(-0.75,-2.155) 15(-0.25,-2.155) 16(0.25,-2.155) 17(0.75,-2.155) 18(1.25,-2.155)
  rrect50% 0.85x0.3 smd: 7(-2.155,1.25) 8(-2.155,0.75) 9(-2.155,0.25) 10(-2.155,-0.25) 11(-2.155,-0.75) 12(-2.155,-1.25) 19(2.155,-1.25) 20(2.155,-0.75) 21(2.155,-0.25) 22(2.155,0.25) 23(2.155,0.75) 24(2.155,1.25)
  rrect5% 2.7x2.7 smd paste-2.718: EXP(0,0)
  body extent -2.05,-2.05 2.05,2.05, height 1
X1-DFN1006-2 [mm] "DFN, 2-Leads, Body 0.61x1.01mm, Pitch 0.65mm, IPC High Density"
  rrect50% 0.4x0.7 smd: 1(-0.35,0) 2(0.35,0)
  body extent -0.54,-0.34 0.54,0.34, height 0.53
XT30UPB-M-Footprint-1 [mm]
  round 2.7 / inner round 1.524 / far side round 2.7 hole 1.8 unplated: +(0,0)
  round 2.7 hole 1.8 unplated: -(0,-5)
  body extent -2.75,-7.62 2.55,2.78, height 12.6

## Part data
B1: library part AF0003-A.2, "Nano board socket + outline"
BATT+1 TP2 TP4 TP5 TP6 TP7 TP8 TP9 TP-5V TP-GND TP-VM TP-VM2 VBUS: library part UT0014-A.2, "Test point 1.27mm"
C1 C7 C8 C9 C19 C20 C22 C26 C28 C32 C33 C34 C35 C36 C37 C46 C64: library part C0015-A.3, "CAP CHIP 0402 100nF 50V X5R 10%", Case Code (Imperial)=0402, Case Code (Metric)=1005, Dielectric=X5R, Manufacturer=Murata, Tolerance=10%, Voltage=50V
C2 C3 C38 C40 C49 C50 C52: library part C0061-A.3, "CAP CHIP 1206 10uF 50V X5R 10%", Case Code (Imperial)=0805, Case Code (Metric)=2012, Dielectric=X5R, Manufacturer=Murata, Manufacturer 2=Samsung, Manufacturer Part Number 2=CL31A106KACLNNC, Package=1206, Tolerance=10%, Voltage=50V
C4 C6 C11 C18: library part C0072-A.1, "CAP CHIP 0603 22UF X5R 16V 20%", Case Code (Imperial)=0603, Case Code (Metric)=1608, Dielectric=X5R, Manufacturer=Samsung, Tolerance=20%, Voltage=6.3V
C5 C13 C31 C58: library part C0062-A.3, "CAP CHIP 1206 100UF 10V X5R 20%", Case Code (Imperial)=0805, Case Code (Metric)=2012, Dielectric=X5R, Manufacturer=Samsung, Package=1206, Tolerance=20%, Voltage=10V
C10 C39 C41 C59 C63 CBUS: library part C0044-A.3, "CAP CHIP 0603 1uF 25V X5R 10%", Case Code (Imperial)=0603, Case Code (Metric)=1608, Dielectric=X5R, Manufacturer=KEMET, Manufacturer 2=AVX, Manufacturer Part Number 2=06033D105KAT4A, Tolerance=10%, Voltage=25V
C12 C23 C24 C27: library part C0064-A.3, "CAP CHIP 1210 22uF 25V X5R 10%", Case Code (Imperial)=0805, Case Code (Metric)=2012, Dielectric=X5R, Manufacturer=KEMET, Manufacturer 2=AVX, Manufacturer Part Number 2=12103D226KAT2A, Package=1210, Tolerance=10%, Voltage=25V
C14 C15 C16 C17 C44 C51 C55: library part C0009-A.3, "CAP CHIP 0402 10nF 50V X7R 10%", Case Code (Imperial)=0402, Case Code (Metric)=1005, Dielectric=X7R, Manufacturer=KEMET, Manufacturer 2=AVX, Manufacturer Part Number 2=4025C103KAT2A, Tolerance=10%, Voltage=50V
C21 C57: library part C0089-A.4, "CAP CHIP 0402 6.9nF 50V X7R 10%", Capacitance=6.8nF, Case Code (Imperial)=0402, Case Code (Metric)=1005, Dielectric=X7R, Manufacturer=Yageo, Max Operating Temperature=125°C, Min Operating Temperature=-55°C, Tolerance=10%, Voltage=50V
C25 C60: library part C0090-A.3, "CAP ALUM SMD 220uF 25V 20%", Capacitance=220uF, Case/Package=Radial, Dielectric Material=Aluminium, ESR (Equivalent Series Resistance)=0.16, Leakage Current=55uA, Manufacturer=Panasonic, Max Operating Temperature=105°C, Min Operating Temperature=-55°C, Package Quantity=1, Ripple Current=600mA, Tolerance=20%, Voltage=25V
C29 C48 C53 C65: library part C0076-A.2, "CAP CHIP 0402 2.2UF 6.3V 20%", Case Code (Imperial)=0402, Case Code (Metric)=1005, Dielectric=X5R, Manufacturer=Yageo, Tolerance=20%, Voltage=6.3V
C30 C54: library part C0073-A.1, "CAP CHIP 0402 1.8NF 25V C0G 5%", Case Code (Imperial)=0402, Case Code (Metric)=1005, Dielectric=C0G, Manufacturer=KEMET, Tolerance=5%, Voltage=25V
C42 C43: library part C0029-A.3, "CAP CHIP 0402 22pF 50V C0G 5%", Case Code (Imperial)=0402, Case Code (Metric)=1005, Dielectric=C0G, Manufacturer=KEMET, Manufacturer 2=AVX, Manufacturer Part Number 2=04025A220JAT2A, Tolerance=5%, Voltage=50V
C45 C56: library part C0074-A.1, "CAP CHIP 0402 150PF 50V C0G 1%", Case Code (Imperial)=0402, Case Code (Metric)=1005, Dielectric=C0G, Manufacturer=Murata, Tolerance=1%, Voltage=50V
C47: library part C0036-A.3, "CAP CHIP 0402 47nF 50V X5R 10%", Case Code (Imperial)=0402, Case Code (Metric)=1005, Dielectric=X5R, Manufacturer=Murata, Tolerance=10%, Voltage=50V
C61 C62: library part C0021-A.3, "CAP CHIP 0402 110pF 50V C0G 5%", Case Code (Imperial)=0402, Case Code (Metric)=1005, Dielectric=C0G, Manufacturer=Murata, Tolerance=5%, Voltage=50V
CN1: library part J0068-A.5, "CONN CONN STRIP THD 1,27 M/2/D 10v AuF H6,3 JTAG", Manufacturer="Adam Tech"
D1 D2 D3 D4: library part D0039-A.1, "DIOEDE TVS ZENER 3.3V ESD PROTECTION", Breakdown Voltage=6.5V, Clamping Voltage=7V, Manufacturer="Diodes Inc.", Max Operating Temperature=150°C, Max Power Dissipation=35W, Max Reverse Leakage Current=100nA, Max Reverse Voltage (DC)=3.3V, Min Breakdown Voltage=3.8V, Min Operating Temperature=-65°C, Package Quantity=10000, Peak Pulse Current=5A, Power Line Protection=No
D5 D6 D7 D8 D9 D10 D11 D12: library part D0026-A.2, "DIODE SCHOTTKY SMD 1A 40V SOD123FL", Manufacturer=Nexperia
DL1 DL2 DL3 DL4 DL5 DL6 DL7 DL8: library part L0008-A.3, "LED SMD 0603 GIA588   8mcd 120^", Manufacturer=Kingbright
DL9 DL10 DL12: library part L0006-A.3, "LED SMD 0603 ORANGE601 250mcd 120^", Manufacturer=Kingbright
fid1 fid2 fid3: library part UT0000-A.2
IC1: library part U0040-A.2, "IC ATSAM-D11-D14A-MUT", Manufacturer=Microchip
IN1 IN2 IN3 IN4: library part J0021-A.2, "CONN M.C.S. DIR BLC p2,54 3v", Manufacturer="Adam Tech"
J6: library part J0002-A.3, "CONN LIPO BATTERY", Manufacturer=AMASS
JANALOG1: library part J0055-A.4, "CONN THD SOCKET F/1/D 15V JANALOG NANO-TYPE"
JDIGITAL1: library part J0056-A.4, "CONN THD SOCKET F/1/D 15V JDIGITAL NANO-TYPE"
L1 L3: library part I0036-A.3, "1.2µH Shielded Wirewound Inductor 18A 5.83mOhm Max Nonstandard (6.60mm x 6.40mm)", Manufacturer="Bourns Inc."
L2: library part I0017-A.3, "IND FIXED 2.2UH 4A 61 MOHM SMD", Current=4A, Manufacturer=Bourns
ON: library part L0009-A.3, "LED SMD 0603 GREEN/568 15mcd 120^", Manufacturer=Broadcom
P1 P2: library part J0054-A.3, "CONTACT SPRING LOADED T/H GOLD", Manufacturer="Mill-Max Manufacturing Corp"
Q1 Q5: library part T0016-A.3, "MOSFET N-CH 30V 21A 8DFN", Case/Package="DFN (3x3)", Continuous Drain Current (ID)=34A, Drain to Source Voltage (Vdss)=30V, Manufacturer="Alpha & Omega Semiconductor", Max Operating Temperature=150°C, Min Operating Temperature=-55°C
Q3: library part T0007-A.4, "MOSFET P-CH 20V 14.5A 8DFN", Case/Package="DFN EP", Continuous Drain Current (ID)=40A, Drain to Source Voltage (Vdss)=20V, Gate to Source Voltage (Vgs)=8V, Manufacturer="Alpha & Omega Semiconductor Inc.", Max Operating Temperature=150°C, Min Operating Temperature=-55°C, Package Quantity=5000, Power Dissipation=29W
R1 R2 R3 R8 R9 R12 R13: library part R0000-A.3, "RES CHIP 0402 0R 1/16W", Case Code (Imperial)=0402, Case Code (Metric)=1005, Manufacturer=Vishay, Manufacturer 2=Panasonic, Manufacturer Part Number 2=ERJ-S020R00X, Power=63mW, Tolerance=J
R4 R5 R6 R7: library part R0021-A.3, "RES CHIP 0402 140R 1% 1/16W", Case Code (Imperial)=0402, Case Code (Metric)=1005, Manufacturer=Vishay, Manufacturer 2=Panasonic, Manufacturer Part Number 2=ERJ-2RKF1400X, Power=63mW, Tolerance=1%
R10 R17 R18 R21 R34 R50: library part R0001-A.3, "RES CHIP 0402 100K 1% 1/16W", Case Code (Imperial)=0402, Case Code (Metric)=1005, Manufacturer=Vishay, Manufacturer 2=Panasonic, Manufacturer Part Number 2=ERJ-2RKF1003X, Power=63mW, Tolerance=1%
R11 R40 R41 R48: library part R0017-A.5, "RES CHIP 0402 330R 5% 1/16W", Case Code (Imperial)=0402, Case Code (Metric)=1005, Manufacturer=Vishay, Manufacturer 2=Panasonic, Manufacturer Part Number 2=ERJ-2GEJ331X, Power=63mW, Tolerance=5%
R14 R15 R19 R20 R25 R26 R39 R42 R43 R44 R45 R46 R47 R49: library part R0003-A.3, "RES CHIP 0402 10K 1% 1/16W", Case Code (Imperial)=0402, Case Code (Metric)=1005, Manufacturer=Vishay, Manufacturer 2=Panasonic, Manufacturer Part Number 2=ERJ-2RKF1002X, Power=63mW, Tolerance=1%
R16: library part R0014-A.3, "RES CHIP 0402 5K49 1% 1/16W", Case Code (Imperial)=0402, Case Code (Metric)=1005, Manufacturer=Vishay, Manufacturer 2=Panasonic, Manufacturer Part Number 2=ERJ-2RKF5491X, Power=63mW, Tolerance=1%
R22 R33: library part R0171-A.4, "RES CHIP 0402 300K 1% 1/16W", Case Code (Imperial)=0402, Case Code (Metric)=1005, Manufacturer=Yageo, Max Operating Temperature=155°C, Min Operating Temperature=-55°C, Power Rating=63mW, Resistance=300kR, Temperature Coefficient=100ppm/°C, Tolerance=1%, Voltage Rating=50V
R23 R35: library part R0068-A.4, "RES CHIP 0402 27K 5% 1/16W", Case Code (Imperial)=0402, Case Code (Metric)=1005, Manufacturer=Vishay, Manufacturer 2=Panasonic, Manufacturer Part Number 2=ERJ-2GEJ273X, Power=63mW, Tolerance=5%
R24: library part R0017-A.3, "RES CHIP 0402 330R 5% 1/16W", Case Code (Imperial)=0402, Case Code (Metric)=1005, Manufacturer=Vishay, Manufacturer 2=Panasonic, Manufacturer Part Number 2=ERJ-2GEJ331X, Power=63mW, Tolerance=5%
R27 R37: library part R0172-A.5, "RES SMD 34K OHM 1% 1/16W 0402", Case Code (Imperial)=0402, Case Code (Metric)=1005, Manufacturer=Yageo, Max Operating Temperature=155°C, Max Power Dissipation=63mW, Min Operating Temperature=-55°C, Package Quantity=10000, Power Rating=62.5mW, Resistance=34kR, Temperature Coefficient=100ppm/°C, Tolerance=1%, Voltage Rating=50V
R28 R29 R30 R31: library part R0030-A.3, "RES CHIP 0402 6.81k 1% 1/16W", Case Code (Imperial)=0402, Case Code (Metric)=1005, Manufacturer=Vishay, Manufacturer 2=Panasonic, Manufacturer Part Number 2=ERJ-2RKF6811X, Power=63mW, Tolerance=1%
R32 R36: library part R0138-A.1, "RES CHIP 0402 16K 1/16W 1%", Case Code (Imperial)=0402, Case Code (Metric)=1005, Manufacturer=Vishay, Manufacturer 2=Panasonic, Manufacturer Part Number 2=ERJ-2GEJ163X, Power=63mW, Tolerance=5%
R38: library part R0074-A.5, "RES CHIP 0402 32K4 1% 1/16W", Case Code (Imperial)=0402, Case Code (Metric)=1005, Manufacturer=Vishay, Manufacturer 2=Panasonic, Manufacturer Part Number 2=ERJ-2RKF3242X, Power=63mW, Tolerance=1%
RN2 RN4: library part R0155-A.2, "RES ARRAY 1206 4 RES 1K OHM", Manufacturer=Bourns, Package=1206, Tolerance=5%
SERVO1 SERVO2 SERVO3 SERVO4: library part J0007-A.2, "CONN M.C.S. DIR BLC p2,54 3v ORANGE", Manufacturer="Adam Tech"
TB5 X1A X1B X2A X2B X3A X3B X6A X6B: library part J0012-A.4, "CONN MORS.CS 2v p3,5 10A aLING.VER", Manufacturer=Adimpex
U1: library part U0111-A.2, "IC LEVEL TRANSLATOR BIDIRECTIONAL 4BIT PUSH PULL", Case/Package=TSSOP, Manufacturer="Texas Instruments", Max Operating Temperature=125°C, Min Operating Temperature=-40°C
U2 U8: library part U0013-A.5, "IC BOOST CONV INPUT DISCONNECT 10A 600KHZ", Manufacturer="Monolithic Power Systems"
U3: library part U0043-A.3, "IC 3 axis Acc/Gyro/Mag from Bosch", Manufacturer=Bosch, Part Number=BNO055
U4 U5 U6 U7: library part U0004-A.4, "IC H BRIDGE MOTOR DRIVER 35V 3.2A", Manufacturer=MPS
U9: library part U0044-A.4, "IC BATT.CHRG.CTRL. VQFN24", Manufacturer="Texas Instruments"
U$1: library part S0004-A.2, "SWITCH SLIDE DPDT 200MA", Manufacturer="Nidec Copal Electronics"
XTAL-32768Hz: library part X0003-A.2, "CRYSTAL SMD 32,768K3,2x1,5H,9RoHS", Frequency=32.768kHz, Frequency Tolerance=20ppm, Load Capacitance=12.5pF, Manufacturer=Epson, Manufacturer 2="Geyer Electronic", Manufacturer Part Number 2="KX-327NHT 32,768K", Max Operating Temperature=85°C, Min Operating Temperature=-40°C, Series Resistance=70kR

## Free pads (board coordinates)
  round 3 hole 3 unplated: MH1(2.6,2.66) MH2(47.26,2.64) MH3(47.27,77.39) MH4(2.61,77.41)
  round 0 hole 0.5 unplated: T2(2.9,80) T2(3.8,80) T2(4.7,80) T2(5.6,80) T2(6.5,80) T2(24.8,0) T2(25.9,0) T2(27,0) T2(43.37,79.99) T2(44.27,79.99) T2(45.17,79.99) T2(46.07,79.99) T2(46.97,79.99)

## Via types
v1: diameter 0.706, hole 0.3, Top to Bottom, tented both sides, 206 vias
v2: diameter 0.7, hole 0.3, Top to Bottom, tented both sides, 86 vias
v3: diameter 0.706/0.706/0.706/0.706 (per signal layer), hole 0.3, Top to Bottom, tented both sides, 17 vias
v4: diameter 0.806/0.806/0.806/0.806 (per signal layer), hole 0.4, Top to Bottom, tented both sides, 5 vias
v5: diameter 0.706, hole 0.3, Top to Bottom, 4 vias
v6: diameter 0.7, hole 0.3, Top to Bottom, 1 vias
v7: diameter 0.706, hole 0.3, Top to Bottom, tented bottom, 1 vias

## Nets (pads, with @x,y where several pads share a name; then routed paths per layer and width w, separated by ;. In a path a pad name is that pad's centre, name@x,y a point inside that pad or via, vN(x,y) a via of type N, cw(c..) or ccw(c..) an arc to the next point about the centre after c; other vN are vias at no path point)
+3.3V: B1.2 C1.2 C20.2 C26.2 CN1.1 IC1.24 IN1.1 IN2.1 IN3.1 IN4.1 JANALOG1.2 R11.1 R14.1 R19.2 R20.2 R24.1 R25.1 R26.1 R40.2 U1.1 U3.3 U3.28 U4.4 U5.4 U6.4 U7.4 X2B.2 X3A.1 | length 29.2
  Top w0.2: R40.2@6.63,4.435 6.565,4.5 6.684,4.619 v1(6.684,5.225) ; U6.4@18.675,67.4 18.688,67.413 18.688,68.213 v3(18.95,68.475) ; U4.4@18.675,76.4 18.675,77.275 v1(18.7,77.3) ; R20.2@20.173,48.712 19.598,48.712 R19.2@19.485,48.825 R20.2@20.45,48.825 20.888,48.825 21.463,49.4 v1(21.6,49.4) ; v1(21.264,79) R11.1@22.225,79 ; R25.1@22.15,25.725 22.15,25.71 21.669,25.229 21.669,23.941 CN1.1@22.455,23.155 ; v1(23.413,36.1) 23.419,36.094 23.419,35.506 R14.1@23.425,35.5 R14.1@23.425,35.515 ; v1(25.226,35.977) 25.333,35.977 25.45,35.86 25.45,35.515 C26.2@25.465,35.5 25.465,35.498 25.25,35.282 25.25,34.797 ; U3.3@25.275,34.287 U3.3@25.25,34.312 25.25,34.797 ; U1.1@26.442,46.245 26.442,47.152 v3(26.526,47.152) ; U3.28@26.563,33.75 26.588,33.775 26.843,33.775 27.1,34.032 27.1,34.661 26.983,34.778 25.27,34.778 25.25,34.797
  Top w0.305: v3@26.526,47.3 28.049,47.3 28.472,47.724 C20.2@28.472,47.862 ; IC1.24@27.329,54.149 27.331,54.146 28.494,54.146 28.54,54.1 C1.2@28.565,54.1 ; v1(28.6,53.4) C1.2@28.6,53.87 ; C20.2@28.635,48 28.647,48.012 28.647,48.913 R26.1@28.659,48.925 ; v1(31.3,61.8) 31.323,61.823 31.323,62.598 U7.4@31.325,62.6 ; v1@31.323,70.923 31.323,71.598 U5.4@31.325,71.6 ; R24.1@43.7,5.275 44.525,5.275 v1(44.9,4.9)
  GND w0.4: 1.3,22.6 3.49,22.6 IN1.1@3.55,22.54 ; IN2.1@46.54,17.5 IN2.1@46.5,17.46 46.56,17.4 48.7,17.4
  other v1: 31.322,70.921
+3V8: C52.2 L2.2 R43.1 R47.1 U9.15 U9.16 | length 18.3
  Top w0.3: v1(19.7,17.5) 19.75,17.55 20.135,17.55 R47.1@20.185,17.6 R43.1@20.185,18.475 ; v1(24.179,12.588) 24.257,12.51 24.257,12.281 24.338,12.2 24.338,10.753 24.692,10.399 24.692,10.328 25.295,9.725 C52.2@25.625,9.725 ; v1@24.25,12.588 24.25,13.45 ; U9.15@24.25,14.345 24.25,13.45 ; U9.16@24.75,14.345 24.75,13.626 24.574,13.45 24.25,13.45
  Top w0.6: C52.2@25.468,9.75 L2.2@29,9.75
  Bottom w0.3: v1(19.7,17.5) 19.718,17.482 19.718,16.982 24.019,12.681 v1@24.029,12.681
  other v1: 24.738,10.374
+5V: C5.2 C13.2 C31.2 C49.2 C50.2 C58.2 ON.A R39.2 R42.2 R46.2 R49.2 R50.2 SERVO1.2 SERVO2.2 SERVO3.2 SERVO4.2 TP-5V.X U9.23 | length 54.9
  Top w0.3: SERVO1.2@3.53,40.42 3.733,40.623 7.898,40.623 C58.2@8.1,40.825 ; SERVO3.2@3.54,30.53 3.568,30.503 5.4,30.503 ; 5.375,30.528 5.4,30.503 ; C5.2@8,30.475 7.972,30.503 5.4,30.503 ; C58.2@8.098,40.423 8.562,40.887 12.062,40.887 ; R39.2@11.512,40.887 R39.2@11.575,40.95 R46.2@12.575,40.95 ; R50.2@30.375,41.475 30.375,42.405 31.195,43.225 36.475,43.225 ; R42.2@36.475,41.925 36.475,43.225 ; R49.2@37.6,41.925 37.6,43.225 ; v5(40.725,1.275) 40.9,1.275 ON.A@41.49,1.865 ; C31.2@41.57,40.425 41.9,40.425 C31.2@41.913,40.412 ; C13.2@42,30.375 42.067,30.442 SERVO4.2@46.403,30.442 ; SERVO2.2@46.467,40.412 46.292,40.587 42.113,40.587 C31.2@41.925,40.775 41.595,40.775 39.145,43.225 37.6,43.225 ; 36.475,43.225 37.6,43.225
  GND w0.3: v5(40.725,1.275) 41.8,2.35 41.8,12.928
  Bottom w0.2: v2(31,16.8) 32.345,16.8 TP-5V.X@32.397,16.852
  other v2: 29.411,16.883 30.207,16.968 28.043,18.869 28.911,18.869
+VM: C3.2 C9.2 C12.2 C23.2 C34.2 C40.2 C41.2 C54.1 C59.2 C60.2 Q1.3 R33.2 TP-VM.X U2.3 U5.9 U5.10 U5.11 U7.9 U7.10 U7.11 | length 28.9
  Top w0.2: v1(34.9,16.2) 34.95,16.25 U2.3@35.95,16.25 ; v1(40.452,17.701) 40.452,17.682 40.85,17.284 R33.2@40.85,17.25 ; R33.2@40.825,17.35 40.858,17.383 40.858,18.143 C54.1@40.89,18.175
  Top w0.3: v1(27.551,77.604) 27.553,77.602 28.373,77.602 C9.2@28.375,77.6 ; C34.2@28.465,68.6 28.49,68.6 28.63,68.74 28.63,69.03 v1(29.1,69.5)
  GND w0.3: v1(27.551,77.604) 27.551,77.549 28.4,76.7 32.675,76.7 33.575,75.8 ; v1(29.1,69.5) 31.025,67.575 33.525,67.575
  Bottom w0.2: v1(34.9,16.2) 34.847,16.2 34.197,16.85 34.197,21.699 v1(35.134,22.636) ; v1(37,33) 37.002,33.002 37.002,34.499 TP-VM.X@37.005,34.501 ; v1(40.4,21.35) 40.475,21.275 40.475,17.724 v1(40.452,17.701)
  other v1: 36,27 37,27 38,27 39,27 40,27 36,28 37,28 38,28 39,28 40,28 36,29 37,29 38,29 39,29 40,29 36,30 37,30 38,30 39,30 40,30 36,31 37,31 36,32 37,32 36,33
  other v2: 37.1,62.4 37.8,62.4 37.1,63.1 37.8,63.1 37.1,63.8 37.8,63.8 37.03,72.788 37.805,72.788 37.055,73.513 37.805,73.513 37.055,74.238 37.805,74.238
+VM2: B1.15 C2.2 C8.2 C10.2 C24.2 C25.2 C27.2 C30.1 C35.2 C38.2 C39.2 JANALOG1.15 Q5.3 R22.2 TP-VM2.X U4.9 U4.10 U4.11 U6.9 U6.10 U6.11 U8.3 | length 37.3
  Top w0.2: v1(7.7,16.7) 7.8,16.7 7.865,16.7 8.215,17.05 U8.3@9.2,17.05 ; v1(13.6,18.4) 13.6,18.423 13.717,18.54 R22.2@14.175,18.54 ; JANALOG1.15@17.38,21.68 18.969,20.091 18.969,16.666 C30.1@19,16.635 ; C35.2@21.6,61.325 21.925,61 21.925,60.387 22.125,60.187 v1(22.125,60.05) ; C8.2@21.609,70.4 v1(22.6,70.4)
  Top w0.5: C38.2@13.763,63.912 C38.2@13.775,63.9
  GND w0.2: 8.45,25.7 9.65,24.5 v1(9.8,24.5) ; 17.8,61.7 19.186,61.7 20.836,60.05 v1(22.125,60.05)
  GND w0.3: 17.3,70.8 17.7,70.4 v1(22.6,70.4)
  Bottom w0.2: v1(7.7,16.7) 7.197,17.203 7.197,21.897 v1(9.8,24.5) ; TP-VM2.X@11.625,32.225 11.712,32.138 11.712,31.425 12,31.137 v1(12,31) ; v1(13.05,22.15) 13.05,22.126 13.5,21.676 13.5,18.77 13.503,18.767 13.503,18.497 v1(13.6,18.4)
  other v1: 10,28 11,28 12,28 13,28 14,28 10,29 11,29 12,29 13,29 14,29 10,30 11,30 12,30 13,30 14,30 10,31 11,31 13,31 14,31 13,32 14,32 13,33 14,33 13,34 14,34
  other v2: 11.975,62.6 12.675,62.6 11.975,63.3 12.675,63.3 11.975,64 12.675,64 11.95,72.425 12.65,72.425 11.95,73.225 12.65,73.225 11.95,74.025 12.65,74.025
